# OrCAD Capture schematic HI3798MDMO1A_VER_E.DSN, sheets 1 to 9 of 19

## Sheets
1 SHEET12: size Custom
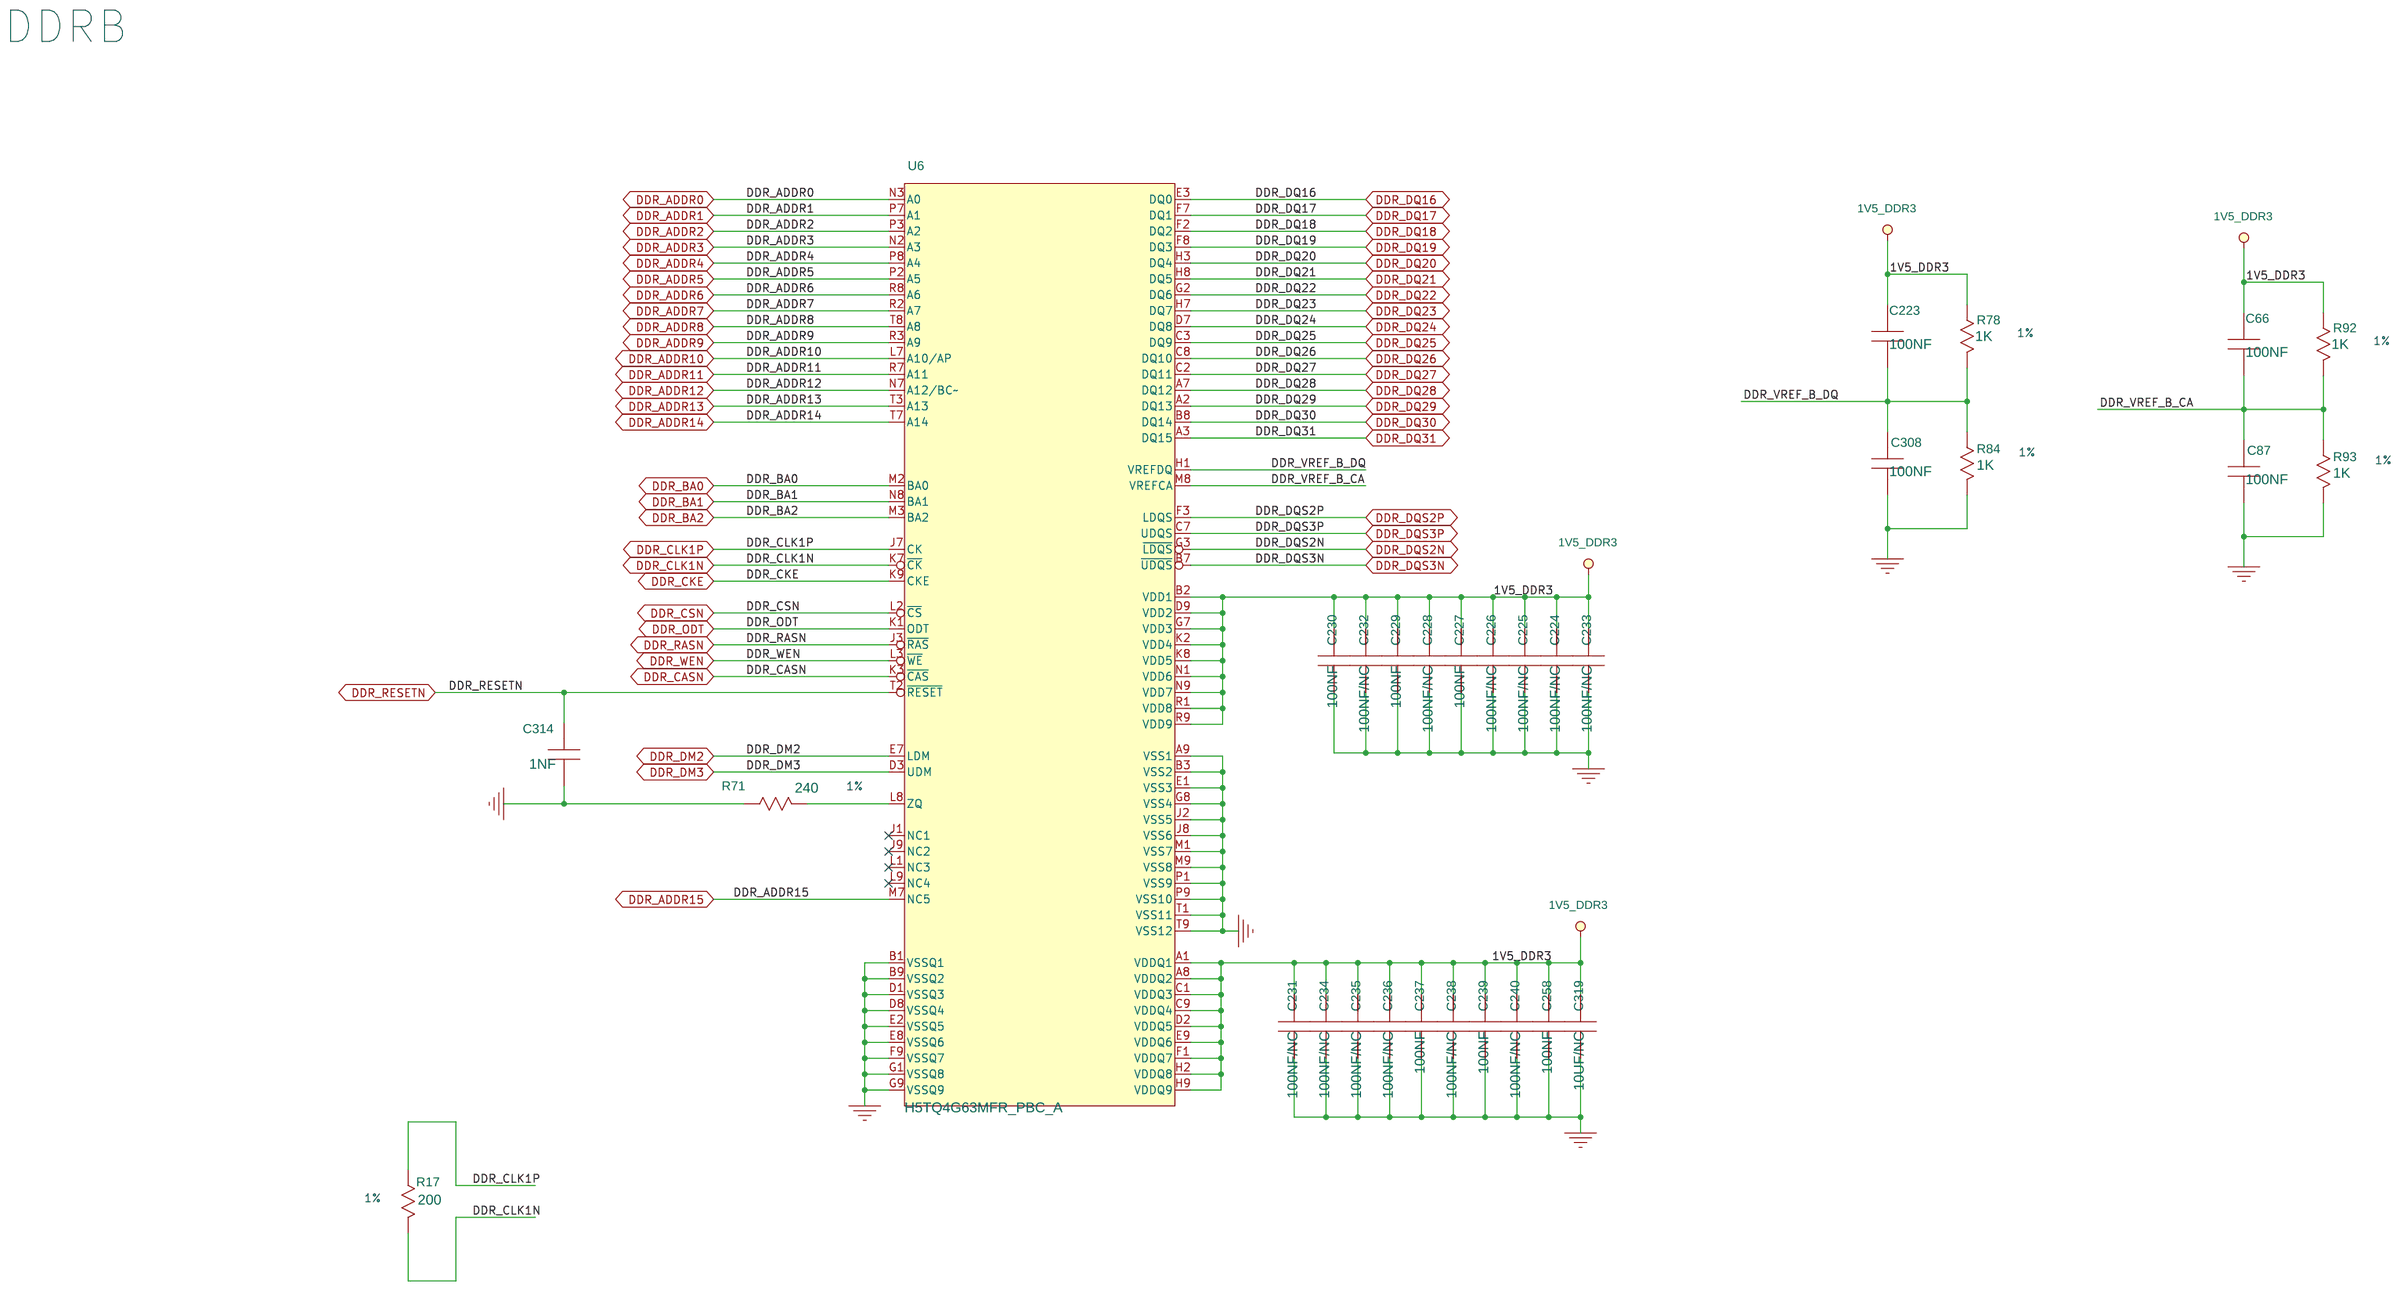
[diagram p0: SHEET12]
2 SHEET11: size Custom
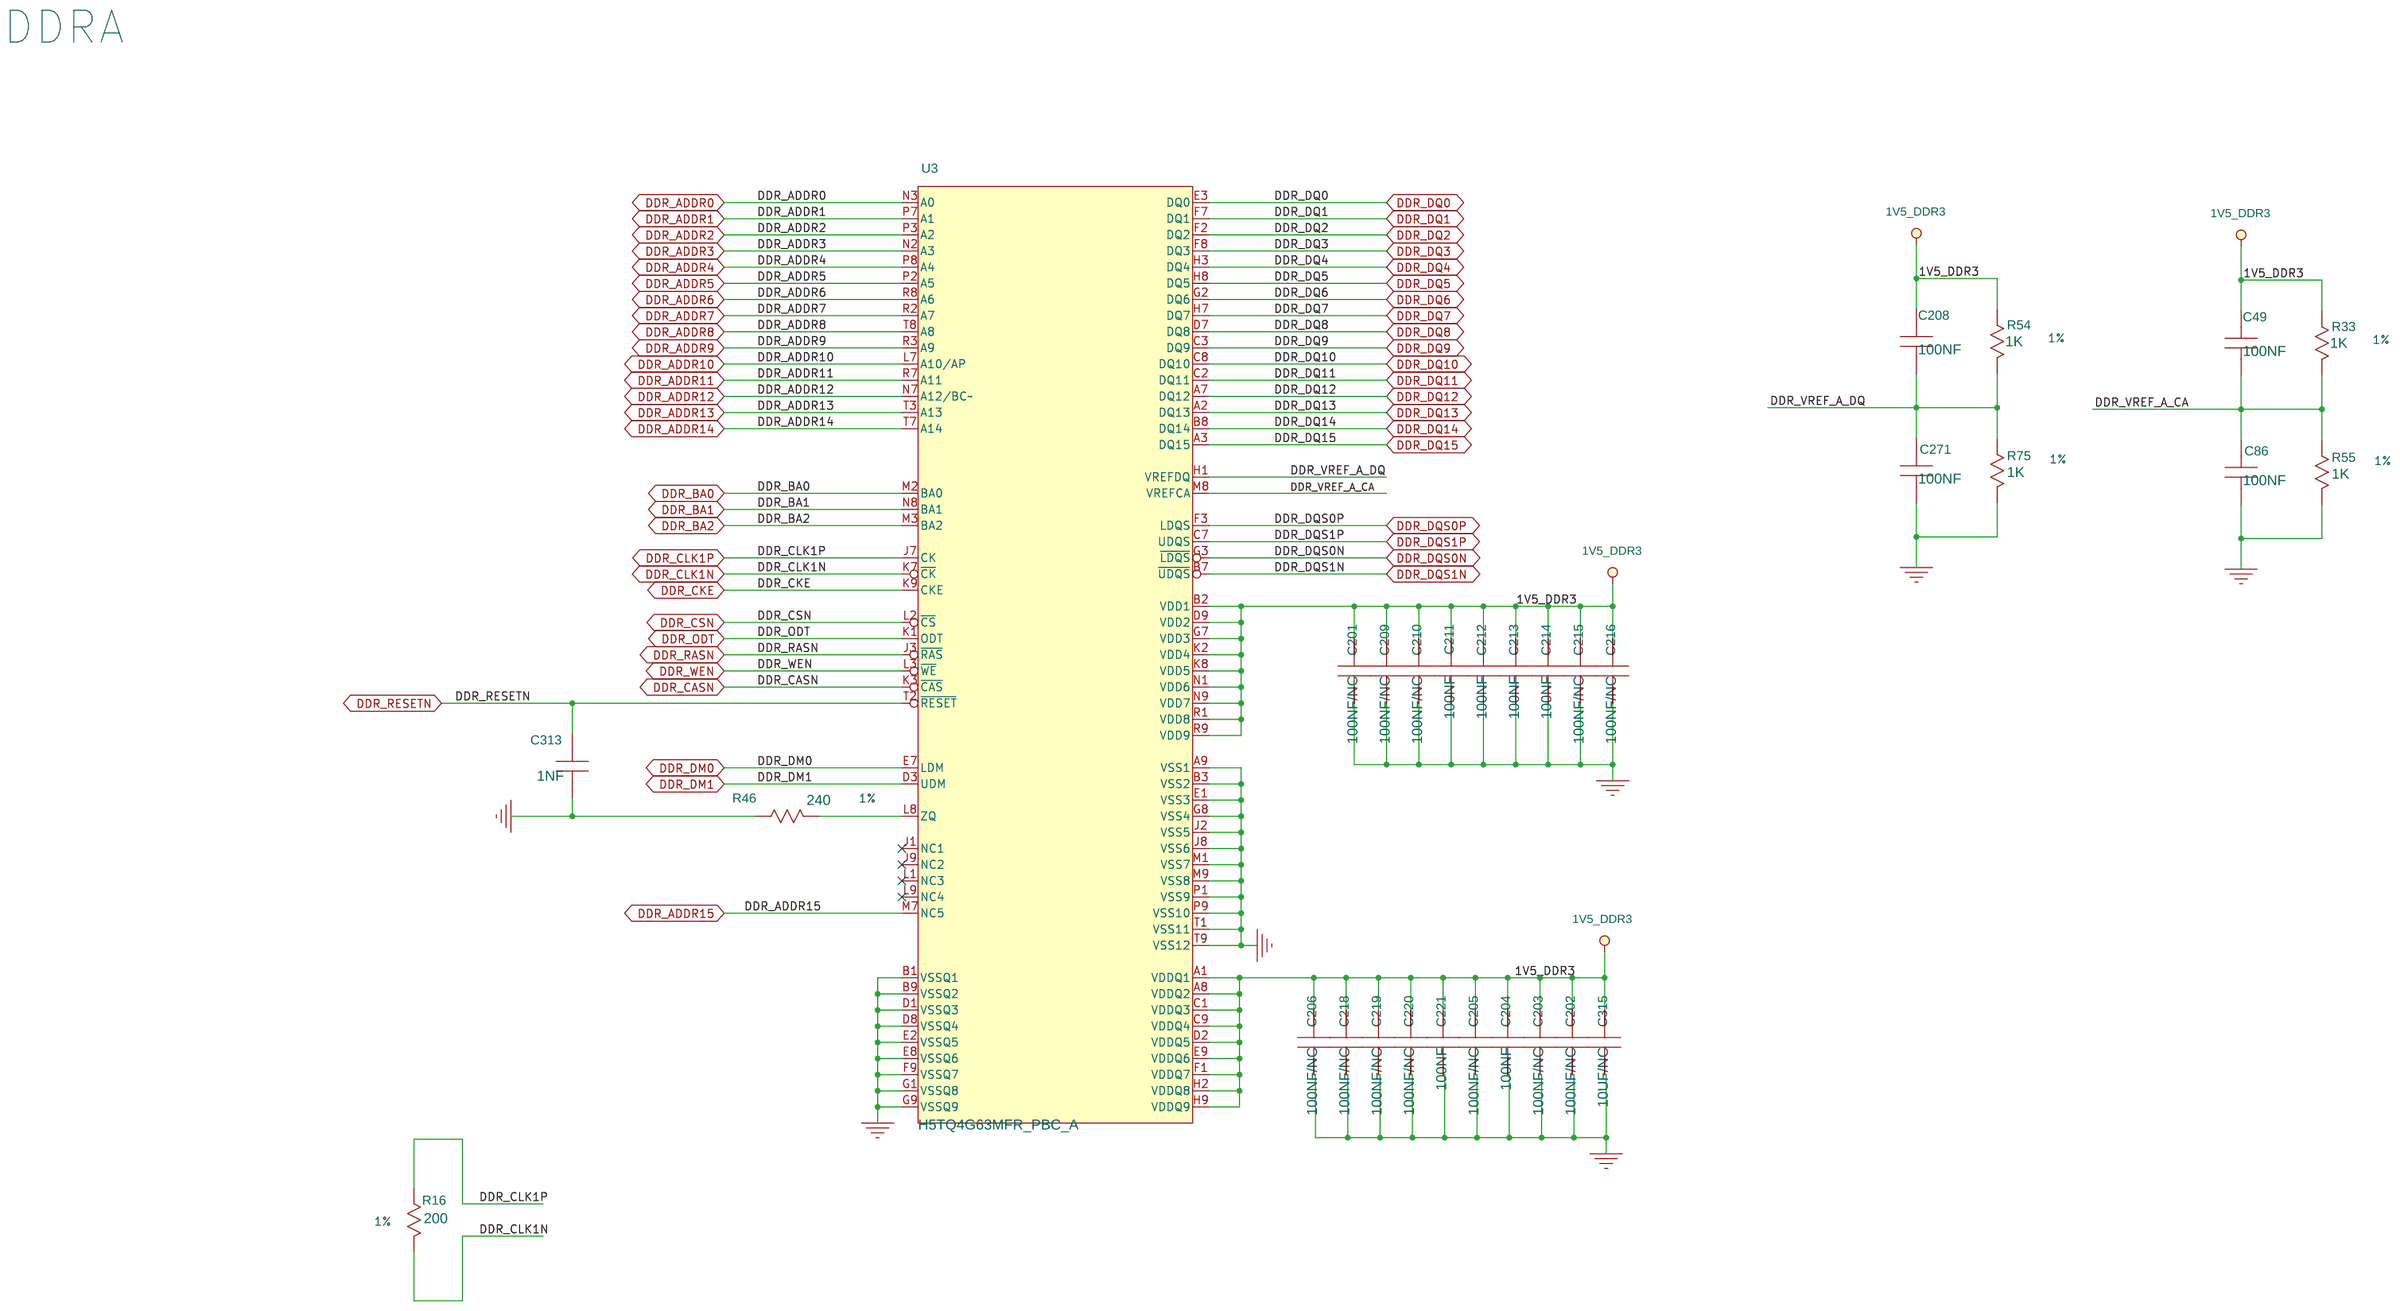
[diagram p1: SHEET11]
3 SHEET01
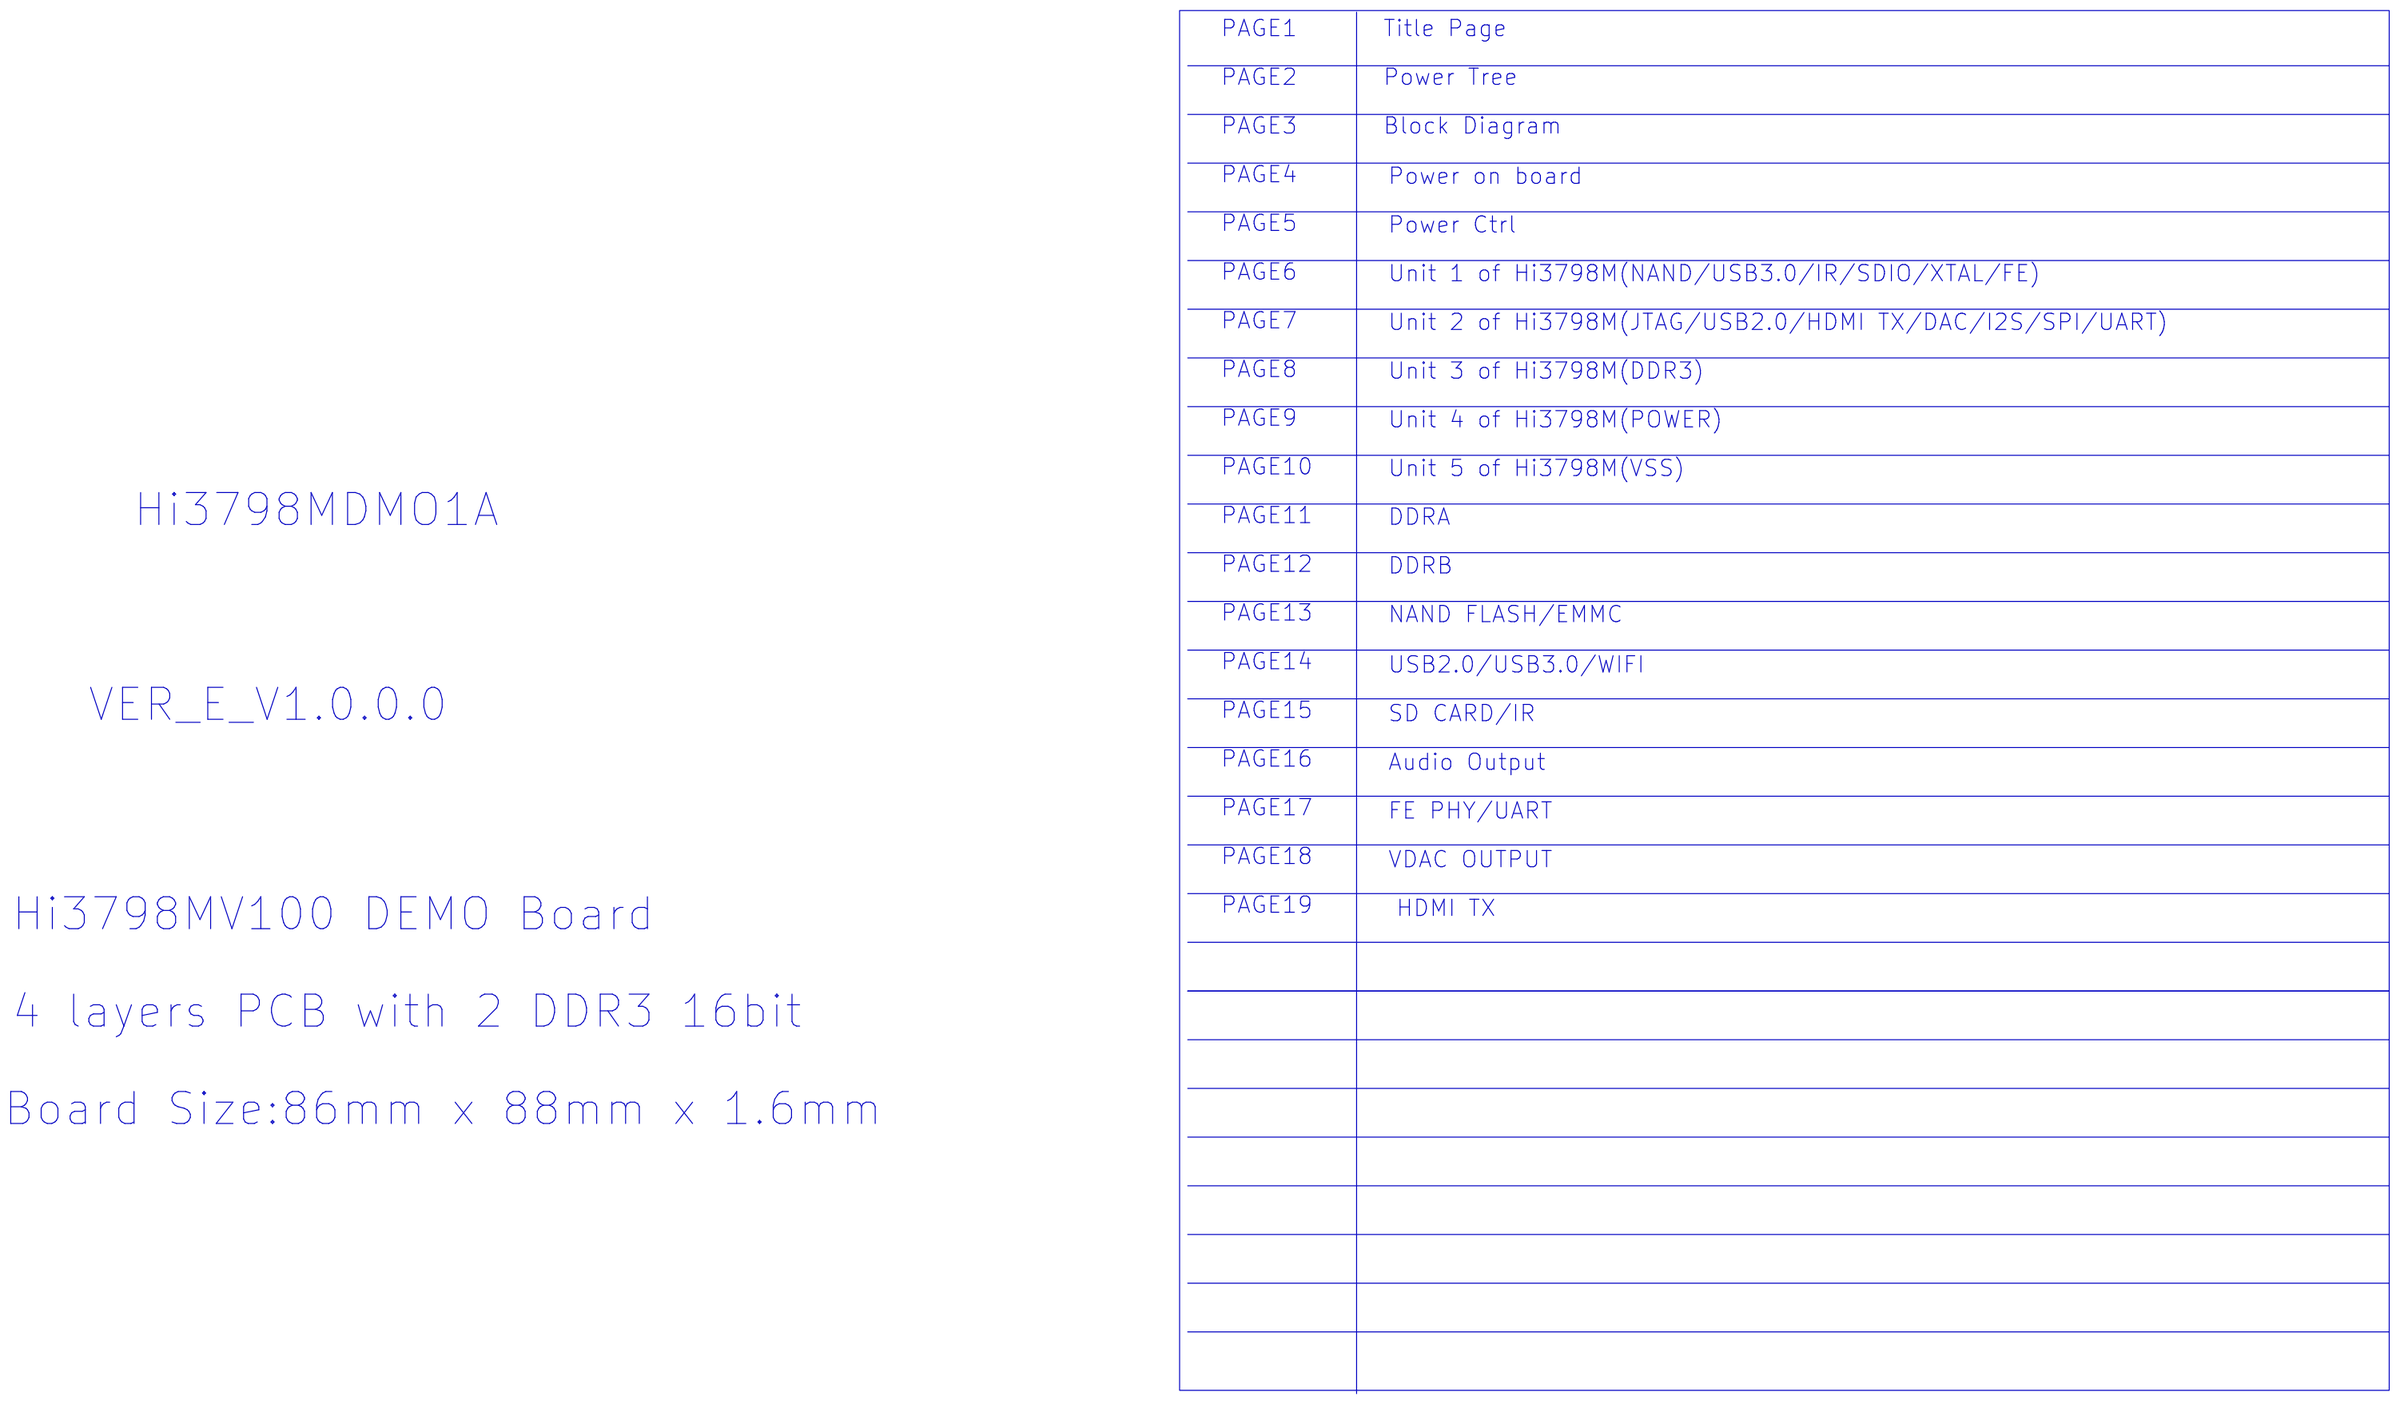
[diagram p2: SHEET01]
4 SHEET02
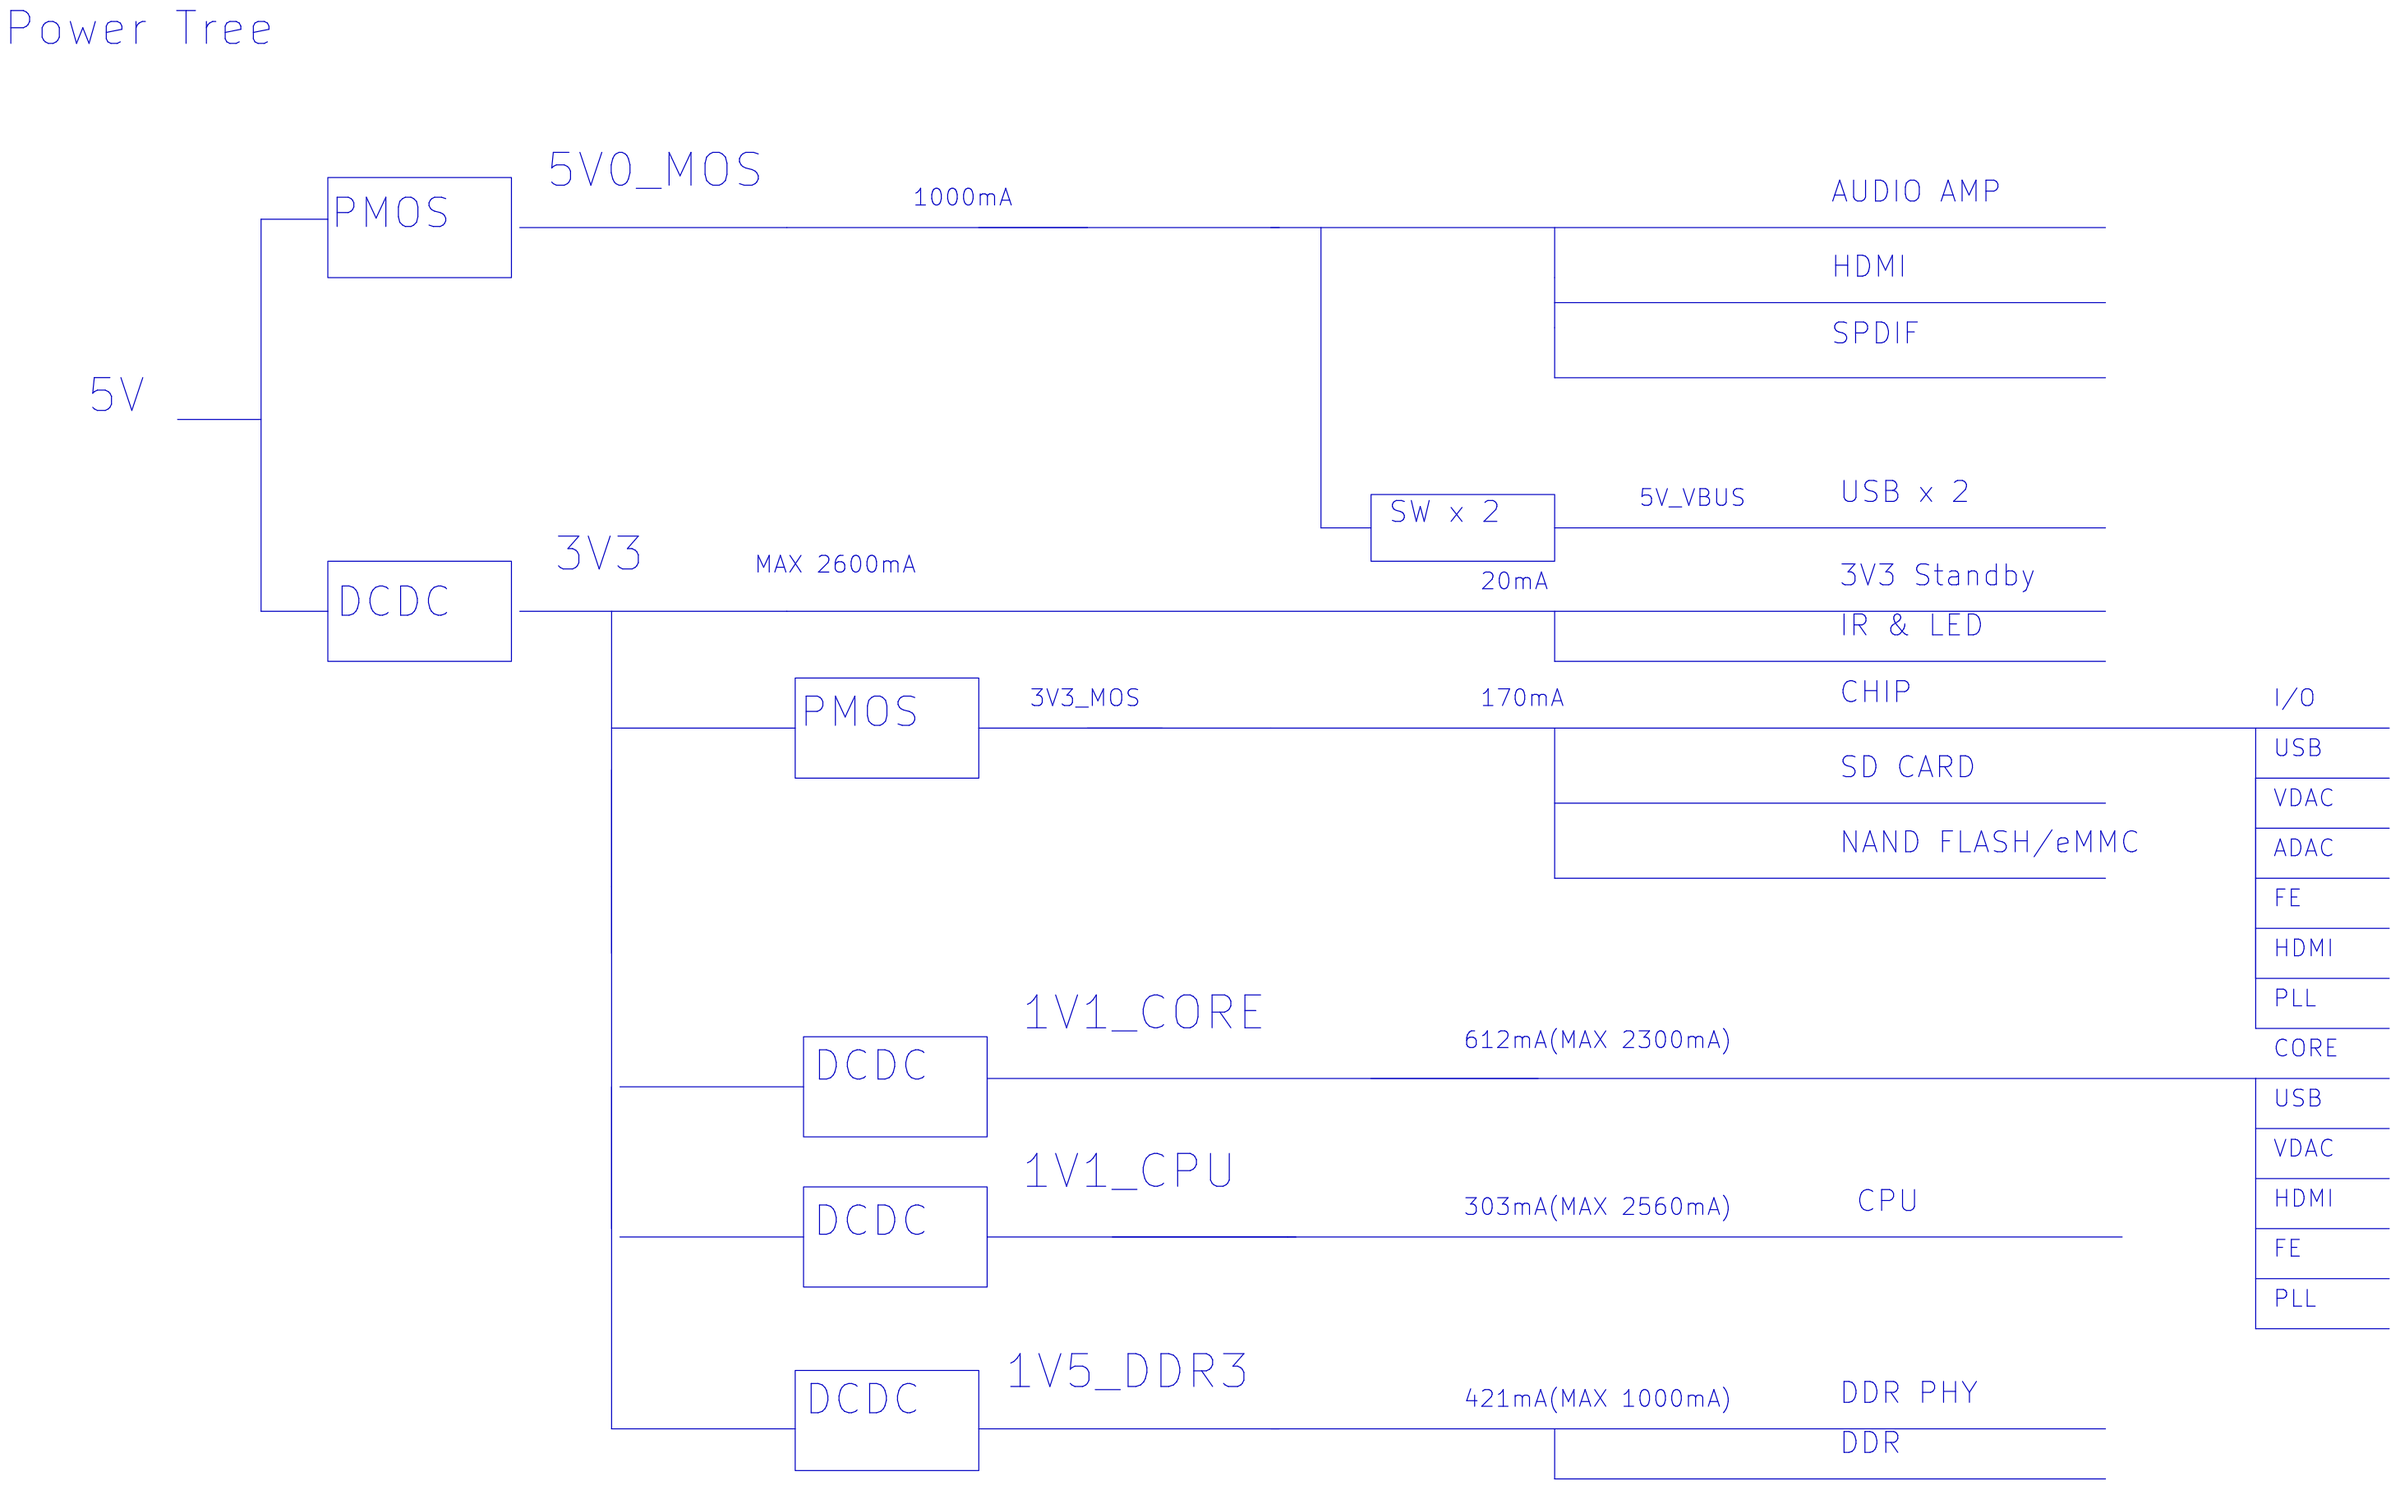
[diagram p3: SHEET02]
5 SHEET03: size B
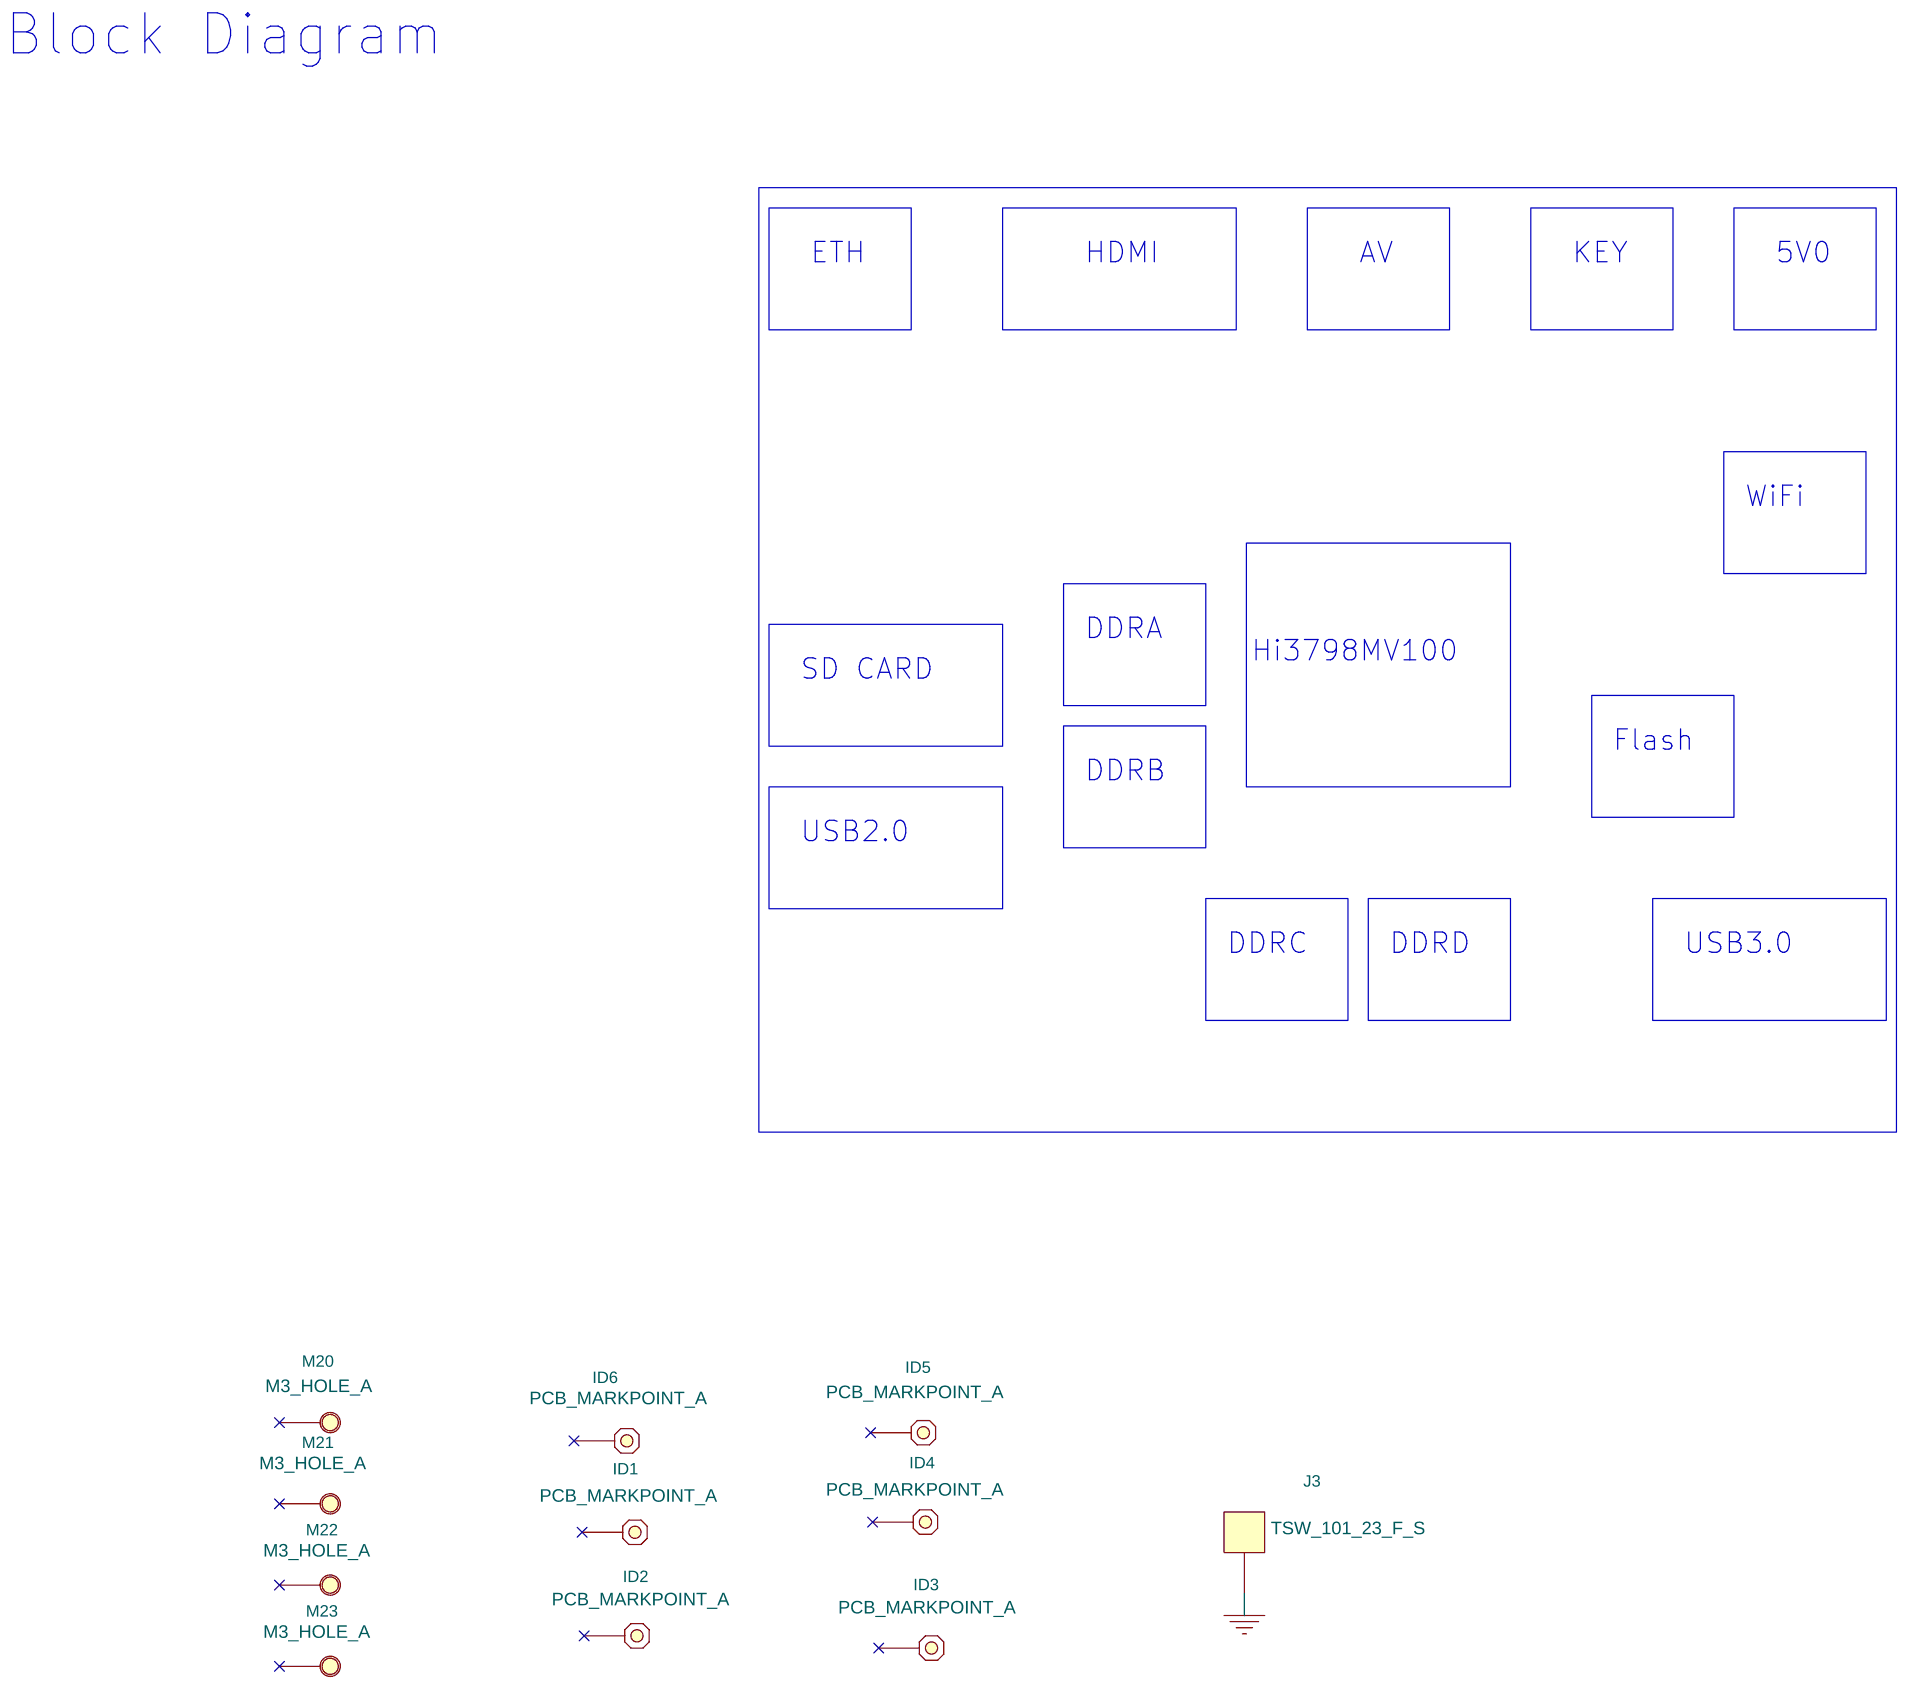
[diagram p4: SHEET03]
6 SHEET04: size Custom
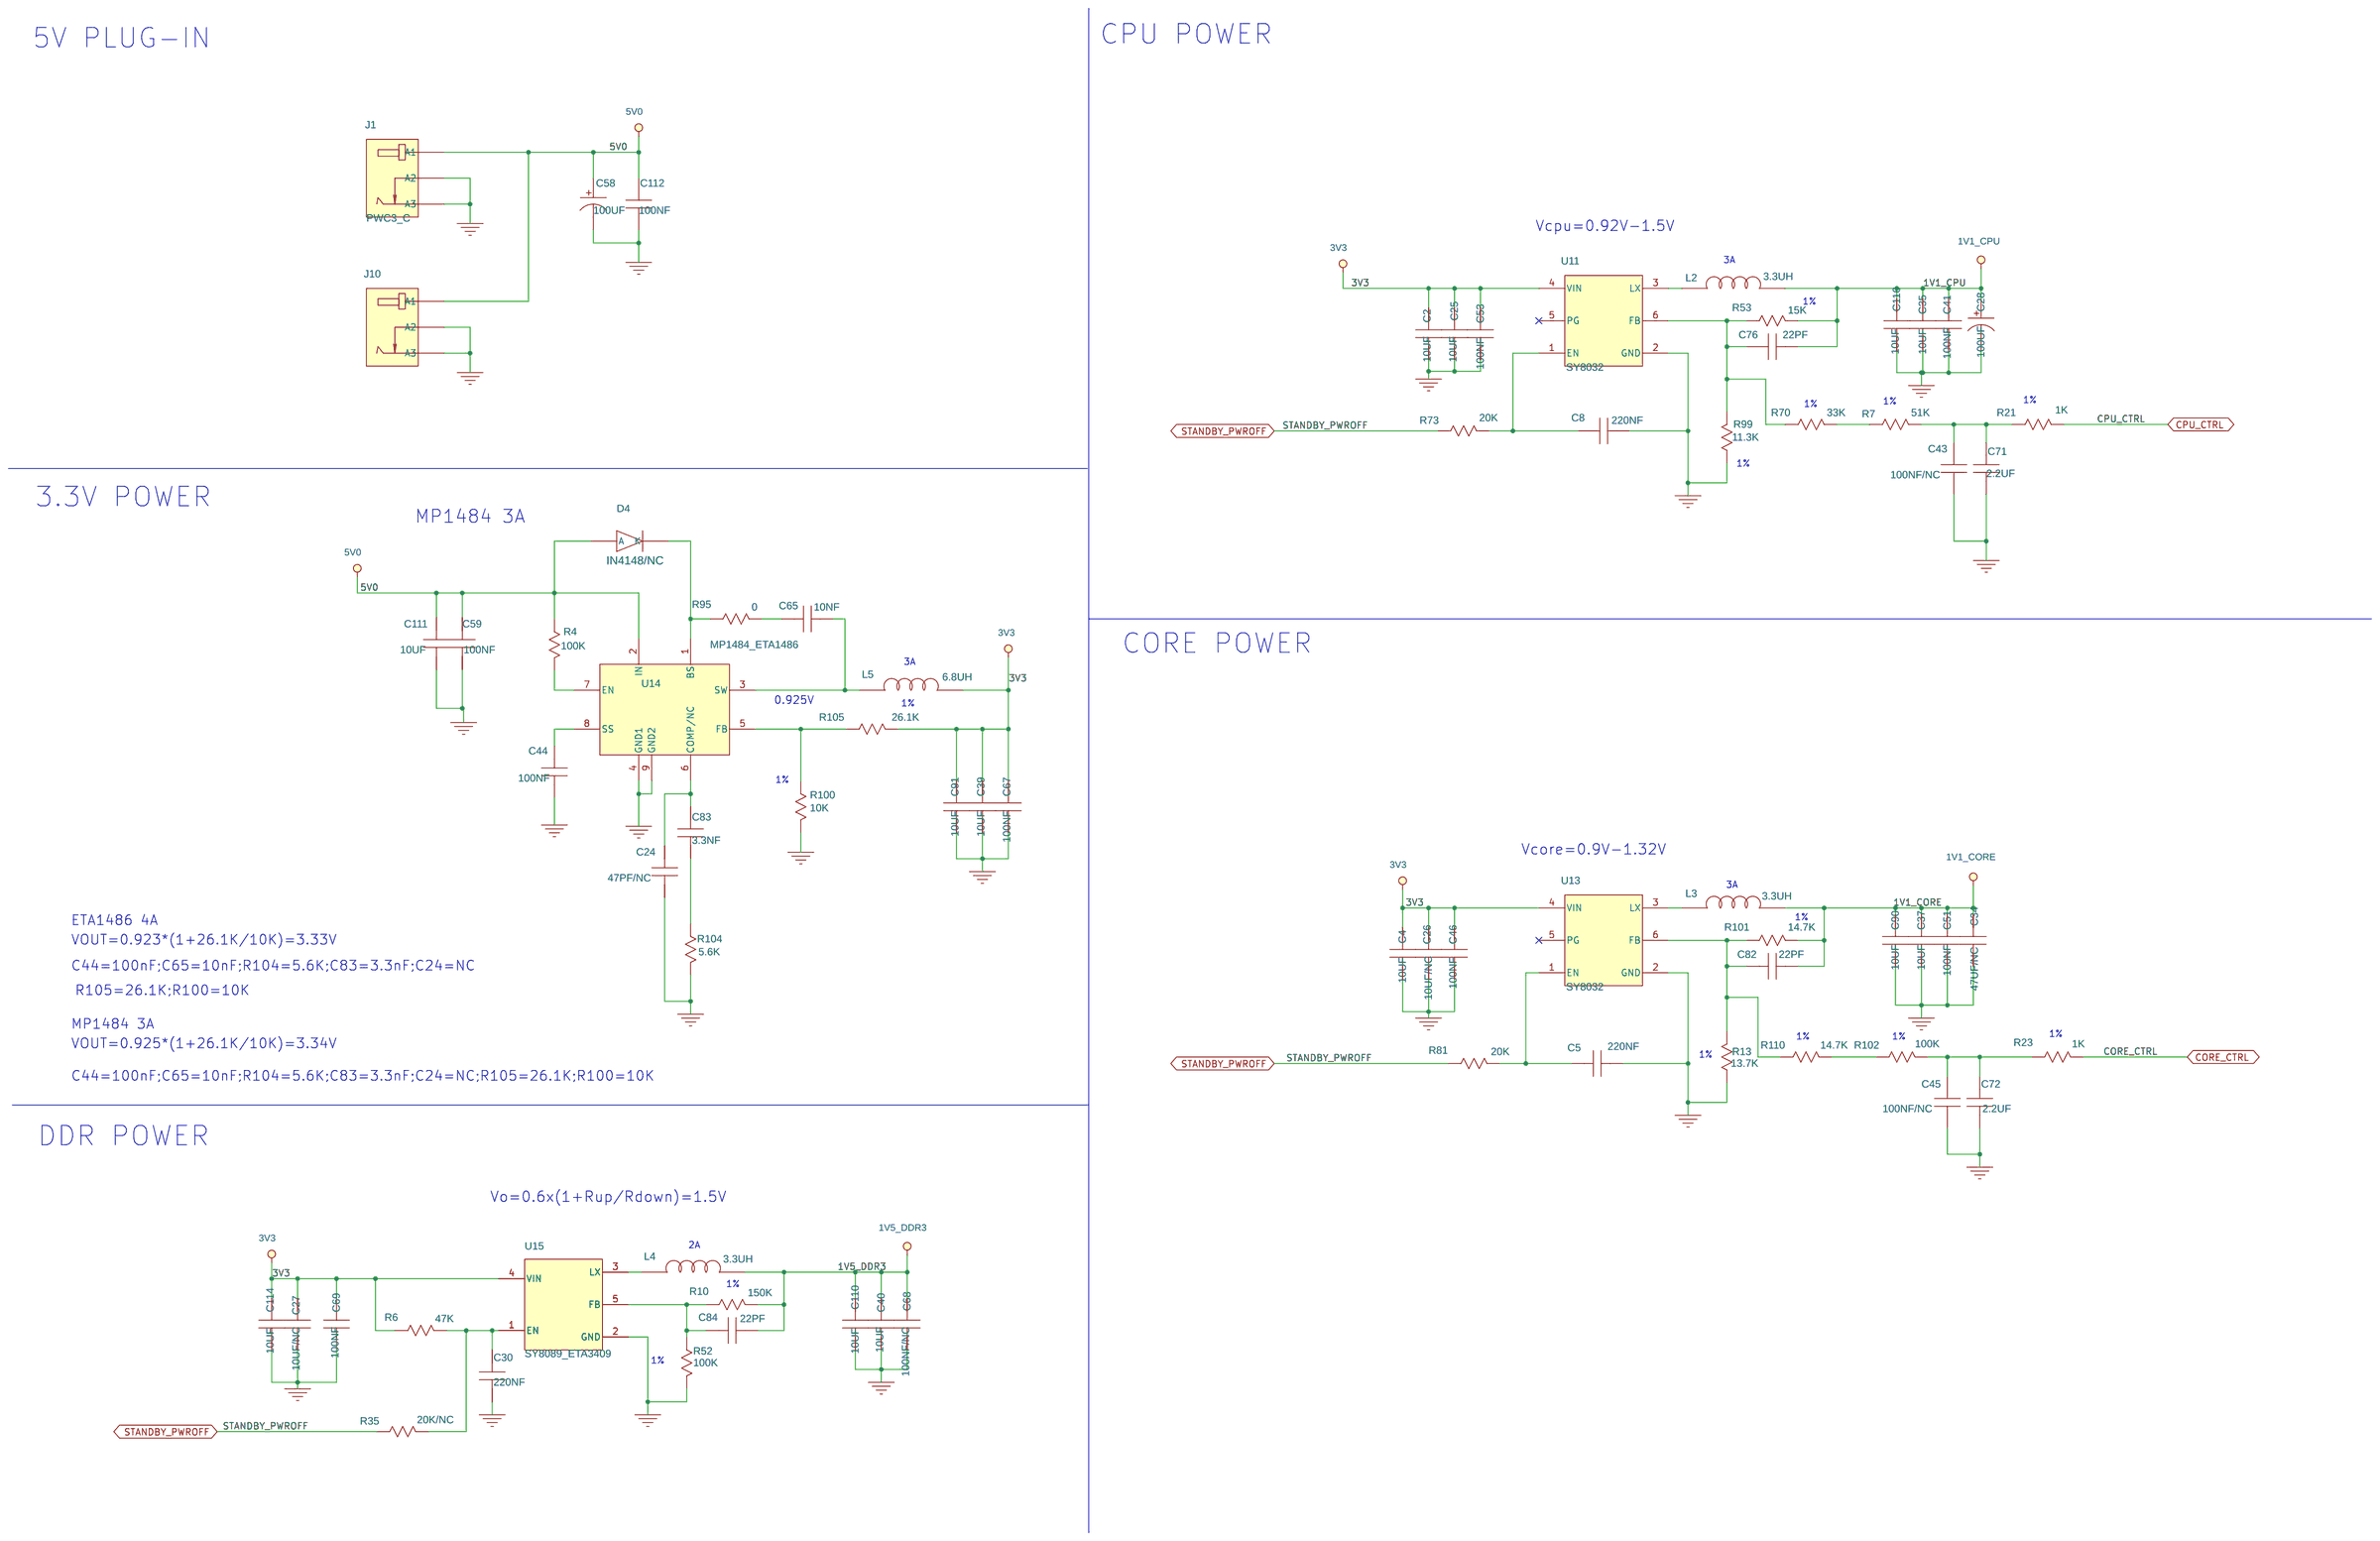
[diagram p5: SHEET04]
7 SHEET05: size A
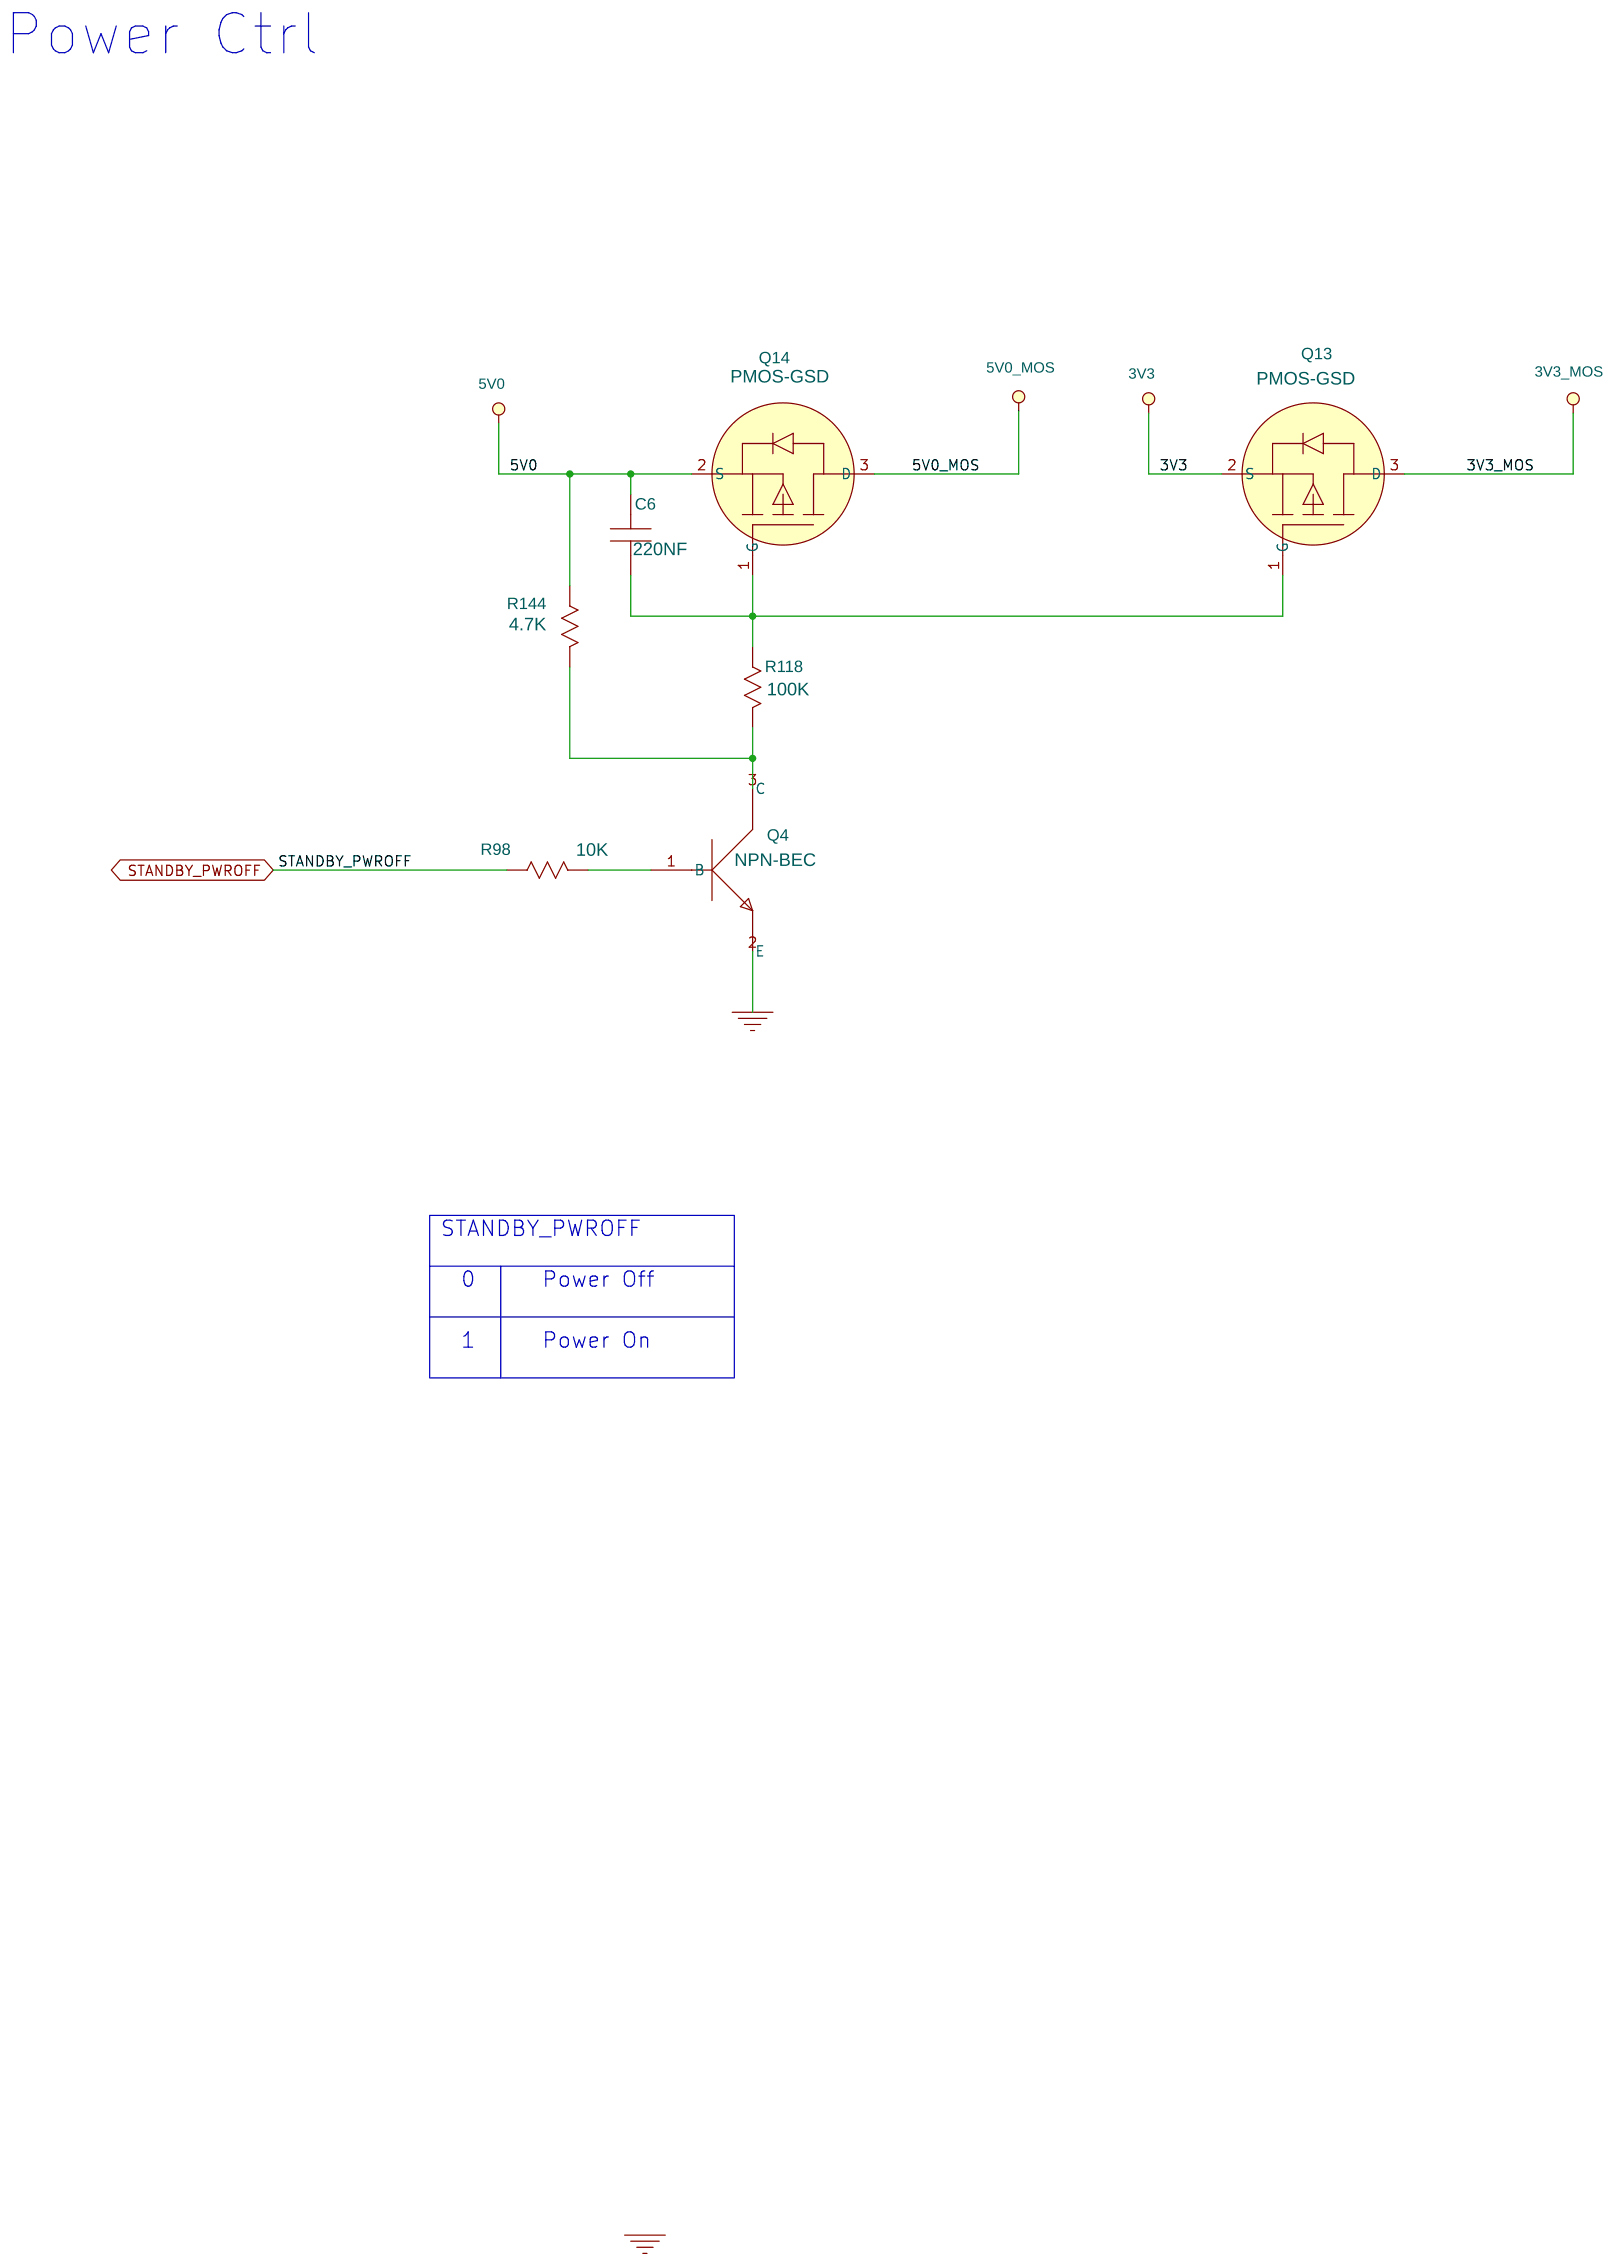
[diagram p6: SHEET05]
8 SHEET06: size Custom
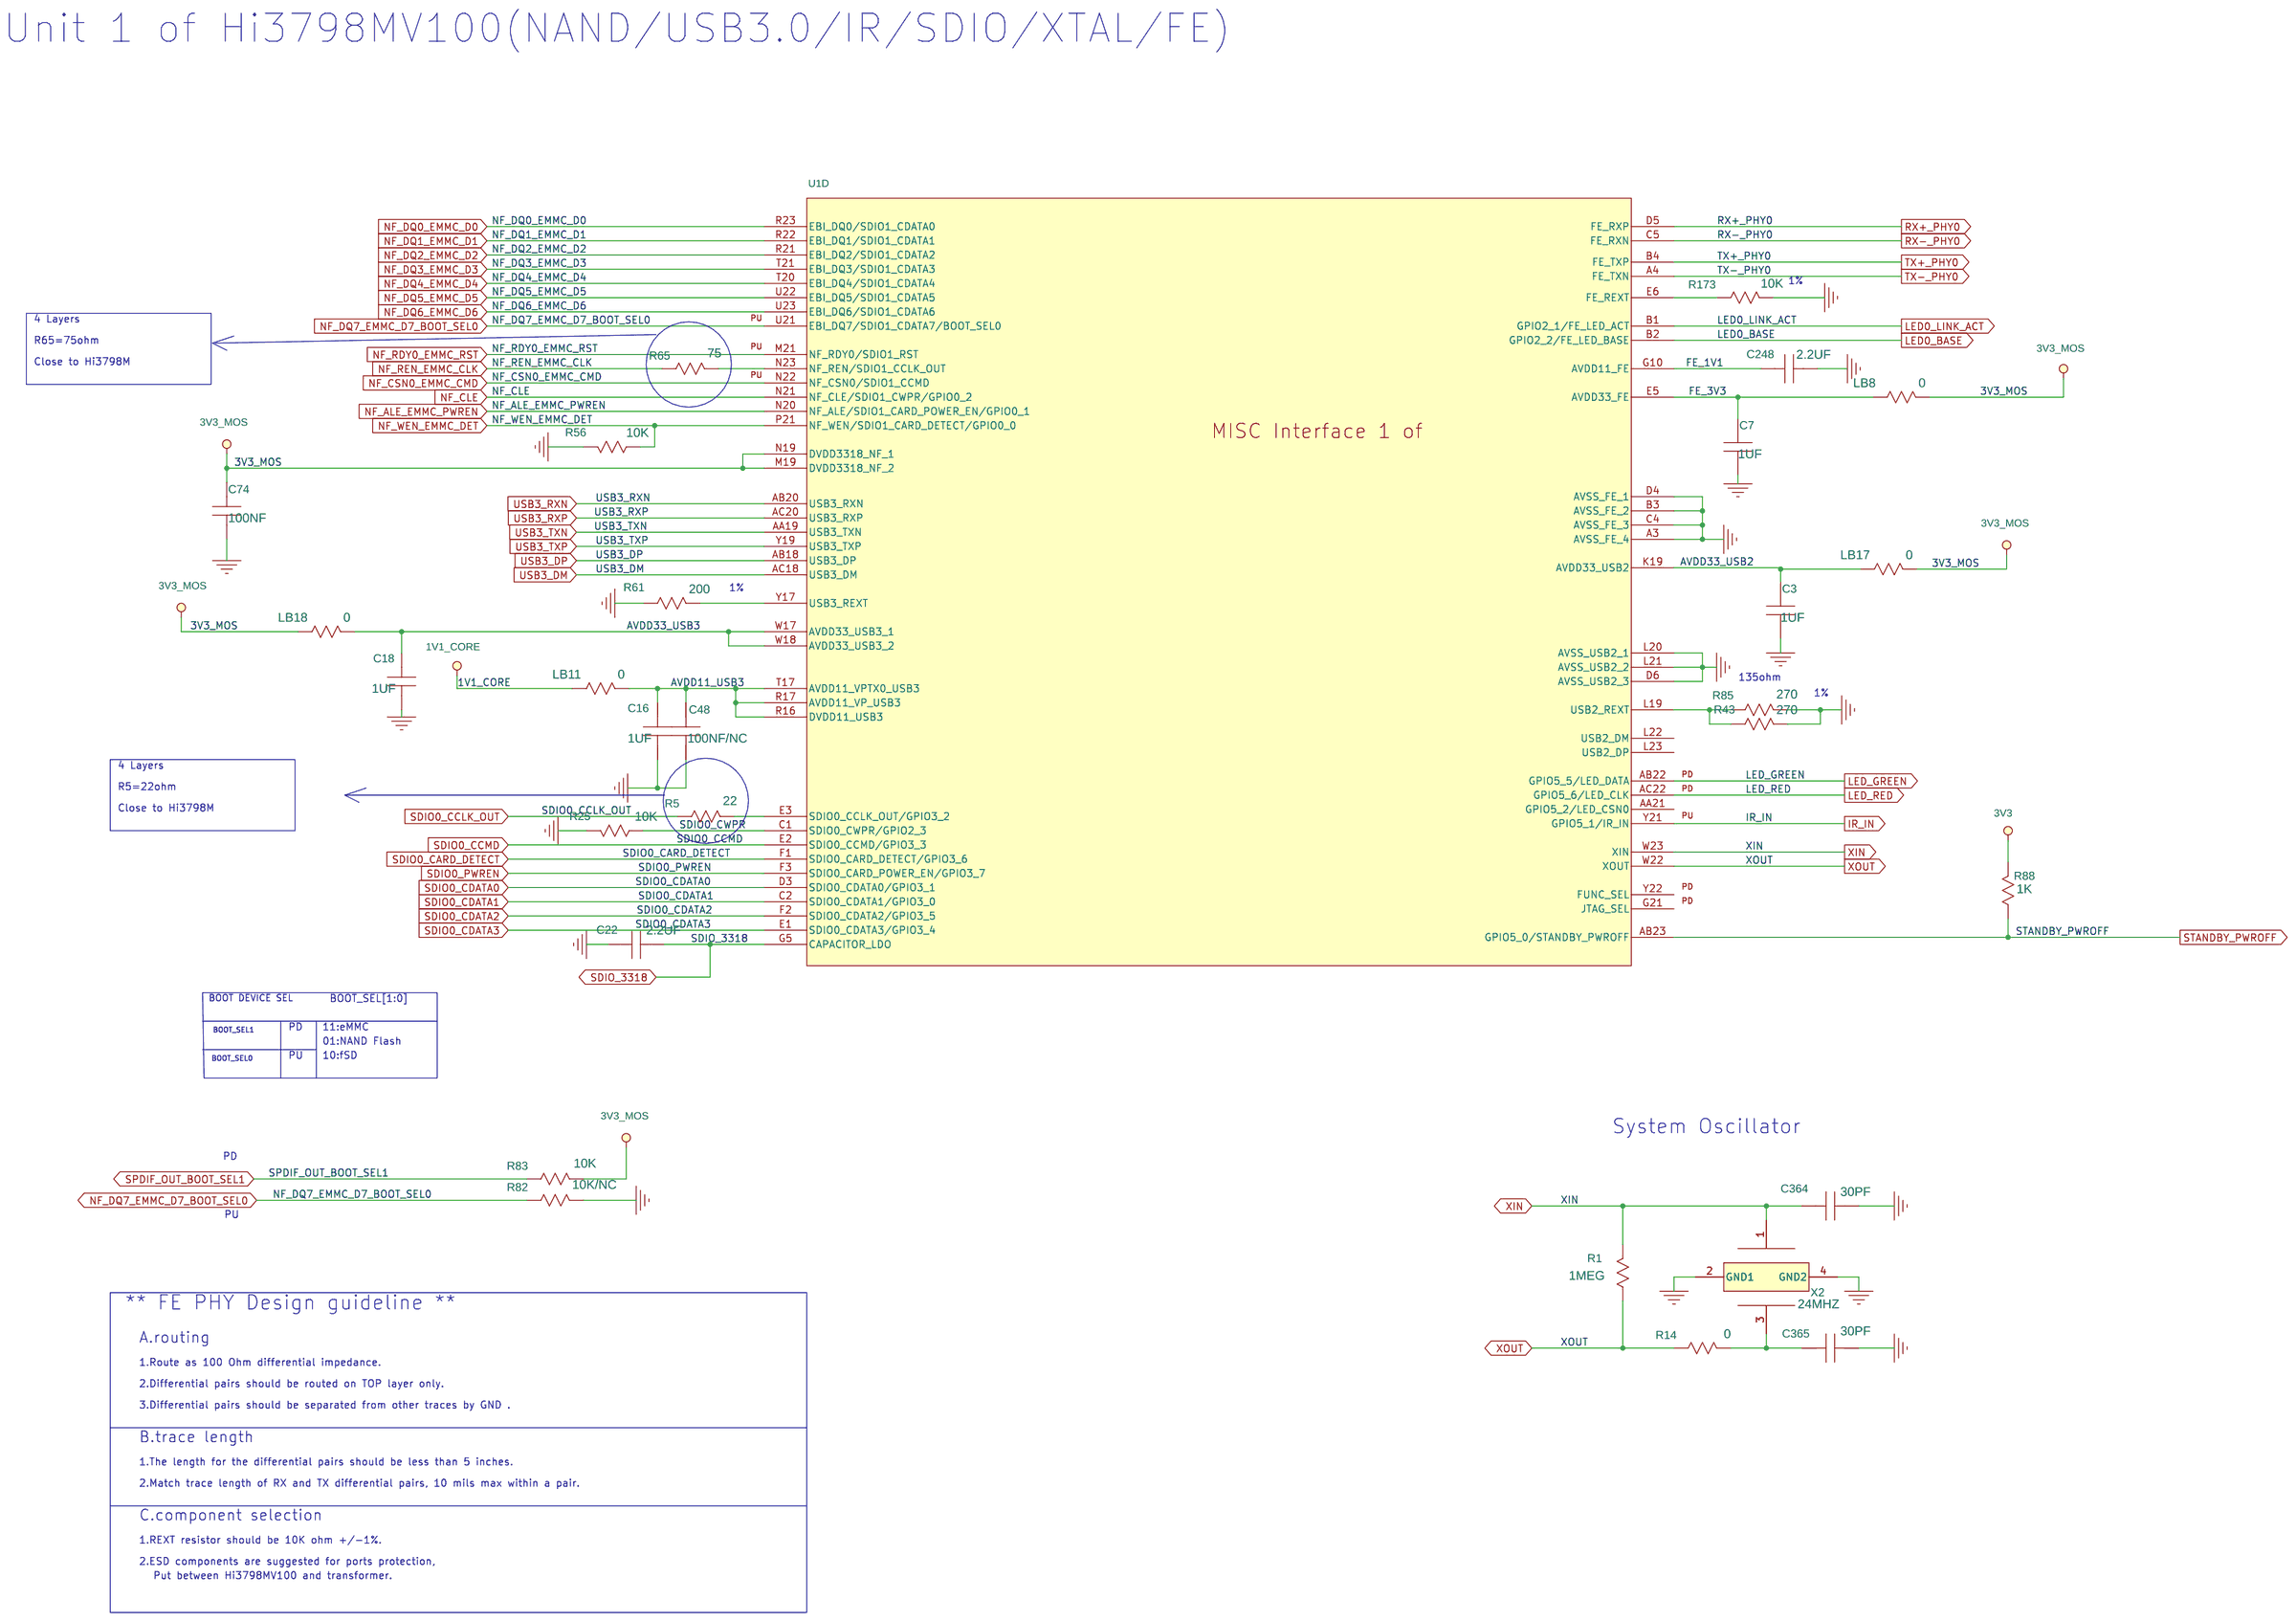
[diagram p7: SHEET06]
9 SHEET07: size Custom
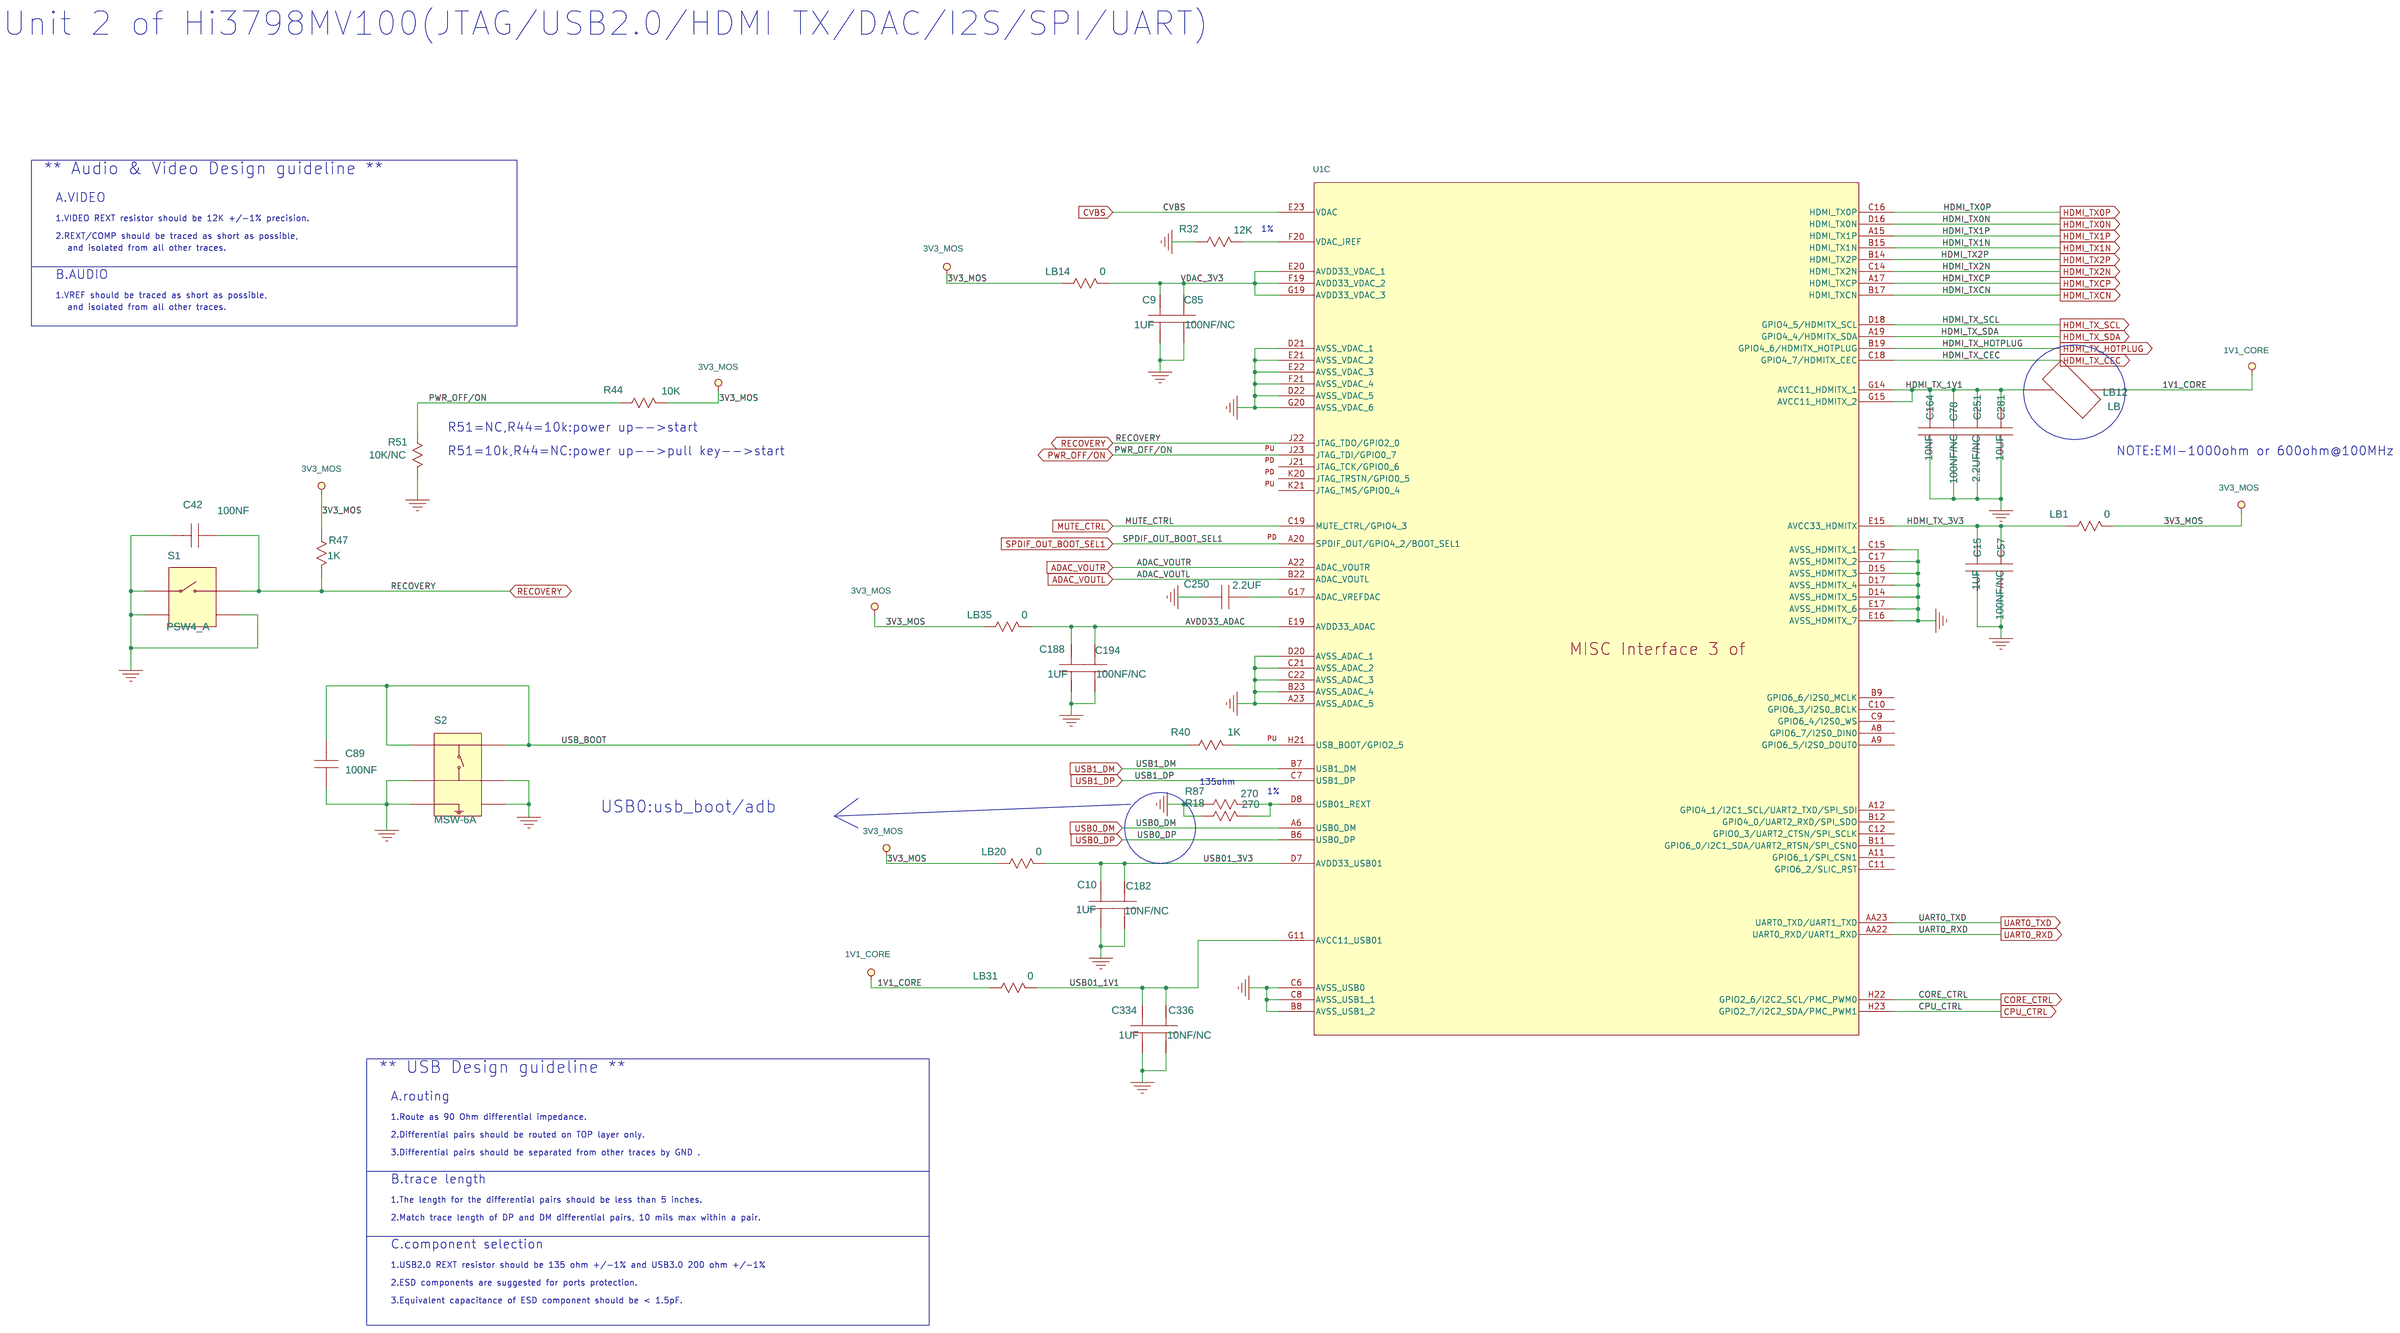
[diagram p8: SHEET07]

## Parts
sheet SHEET03
ID1  ID-BOARD  [ID-BOARD]
ID2  ID-BOARD  [ID-BOARD]
ID3  ID-BOARD  [ID-BOARD]
ID4  ID-BOARD  [ID-BOARD]
ID5  ID-BOARD  [ID-BOARD]
ID6  ID-BOARD  [ID-BOARD]
J3  NC  [SIP-1P]
M20  HOLE  [HOLE182-142]
M21  HOLE  [HOLE182-142]
M22  HOLE  [HOLE182-142]
M23  HOLE  [HOLE182-142]
sheet SHEET04
C2  10UF  [SC0805]
C4  10UF  [SC0805]
C5  220NF  [SC0402]
C8  220NF  [SC0402]
C24  47PF/NC  [SC0402]
C25  10UF  [SC0805]
C26  10UF/NC  [SC0805]
C27  10UF/NC  [SC0805]
C28  100UF  [SAC6666]
C30  220NF  [SC0402]
C34  47UF/NC  [SC1206]
C35  10UF  [SC0603]
C37  10UF  [SC0603]
C39  10UF  [SC0603]
C40  10UF  [SC0603]
C41  100NF  [SC0402]
C43  100NF/NC  [SC0402]
C44  100NF  [SC0402]
C45  100NF/NC  [SC0402]
C46  100NF  [SC0402]
C51  100NF  [SC0402]
C53  100NF  [SC0402]
C58  100UF  [SAC6666]
C59  100NF  [SC0402]
C65  10NF  [SC0402]
C67  100NF  [SC0402]
C68  100NF/NC  [SC0402]
C69  100NF  [SC0402]
C71  2.2UF  [SC0603]
C72  2.2UF  [SC0603]
C76  22PF  [SC0402]
C82  22PF  [SC0402]
C83  3.3NF  [SC0402]
C84  22PF  [SC0402]
C90  10UF  [SC0603]
C91  10UF  [SC0603]
C110  10UF  [SC0603]
C111  10UF  [SC0805]
C112  100NF  [SC0402]
C114  10UF  [SC0805]
C116  10UF  [SC0603]
D4  IN4148/NC  [HSOD323A]
J1  PWC3_C  [PWC3-RF-A]
J10  NC  [DC-002]
L2  3.3UH  [SWPA4020S]
L3  3.3UH  [SWPA4020S]
L4  3.3UH  [SWPA4020S]
L5  6.8UH  [SWPA5040S]
R4  100K  [SR0402]
R6  47K  [SR0402]
R7  51K  [SR0402]
R10  150K  [SR0402]
R13  13.7K  [SR0402]
R21  1K  [SR0402]
R23  1K  [SR0402]
R35  20K/NC  [SR0402]
R52  100K  [SR0402]
R53  15K  [SR0402]
R70  33K  [SR0402]
R73  20K  [SR0402]
R81  20K  [SR0402]
R95  0  [SR0402]
R99  11.3K  [SR0402]
R100  10K  [SR0402]
R101  14.7K  [SR0402]
R102  100K  [SR0402]
R104  5.6K  [SR0402]
R105  26.1K  [SR0402]
R110  14.7K  [SR0402]
U11  SY8032  [SOT23_6]
U13  SY8032  [SOT23_6]
U14  MP1484_ETA1486  [SOIC8N]
U15  SY8089_ETA3409  [SOT23_5]
sheet SHEET05
C6  220NF  [SC0603]
Q4  NPN-BEC  [SOT23]
Q13  PMOS-GSD  [SOT23]
Q14  PMOS-GSD  [SOT23]
R98  10K  [SR0402]
R118  100K  [SR0402]
R144  4.7K  [SR0402]
sheet SHEET06
C3  1UF  [SC0603]
C7  1UF  [SC0603]
C16  1UF  [SC0603]
C18  1UF  [SC0603]
C22  2.2UF  [HSC0402]
C48  100NF/NC  [SC0402]
C74  100NF  [SC0402]
C248  2.2UF  [HSC0402]
C364  30PF  [SC0402]
C365  30PF  [SC0402]
LB8  0  [SL0402]
LB11  0  [SL0402]
LB17  0  [SL0603]
LB18  0  [SL0402]
R1  1MEG  [SR0603]
R5  22  [SR0402]
R14  0  [SR0402]
R25  10K  [SR0402]
R43  270  [SR0402]
R56  10K  [SR0402]
R61  200  [SR0402]
R65  75  [SR0402]
R82  10K/NC  [SR0402]
R83  10K  [SR0402]
R85  270  [SR0402]
R88  1K  [SR0402]
R173  10K  [SR0402]
X2  24MHZ  [X288]
sheet SHEET07
C9  1UF  [SC0603]
C10  1UF  [SC0603]
C15  1UF  [SC0402]
C42  100NF  [SC0402]
C57  100NF/NC  [SC0402]
C78  100NF/NC  [SC0402]
C85  100NF/NC  [SC0402]
C89  100NF  [SC0402]
C164  10NF  [SC0402]
C182  10NF/NC  [SC0402]
C188  1UF  [SC0603]
C194  100NF/NC  [SC0402]
C250  2.2UF  [HSC0402]
C251  2.2UF/NC  [SC0603]
C281  10UF  [SC0603]
C334  1UF  [SC0402]
C336  10NF/NC  [SC0402]
LB1  0  [SL0402]
LB12  LB  [SL0402]
LB14  0  [SL0603]
LB20  0  [SL0402]
LB31  0  [SL0402]
LB35  0  [SL0402]
R18  270  [SR0402]
R32  12K  [SR0402]
R40  1K  [SR0402]
R44  10K  [SR0402]
R47  1K  [SR0402]
R51  10K/NC  [SR0402]
R87  270  [SR0402]
S1  PSW4_A  [TSW4-RG-C]
S2  MSW-6A  [SPSW6-T]
sheet SHEET09
U1  S40V300_19X19  [TFBGA395-32-2323]  (sections A,B,C,D,E)
sheet SHEET11
C49  100NF  [SC0402]
C86  100NF  [SC0402]
C201  100NF/NC  [SC0402]
C202  100NF/NC  [SC0402]
C203  100NF/NC  [SC0402]
C204  100NF  [SC0402]
C205  100NF/NC  [SC0402]
C206  100NF/NC  [SC0402]
C208  100NF  [SC0402]
C209  100NF/NC  [SC0402]
C210  100NF/NC  [SC0402]
C211  100NF  [SC0402]
C212  100NF  [SC0402]
C213  100NF  [SC0402]
C214  100NF  [SC0402]
C215  100NF/NC  [SC0402]
C216  100NF/NC  [SC0402]
C218  100NF/NC  [SC0402]
C219  100NF/NC  [SC0402]
C220  100NF/NC  [SC0402]
C221  100NF  [SC0402]
C271  100NF  [SC0402]
C313  1NF  [SC0402]
C315  10UF/NC  [SC0805]
R16  200  [SR0402]
R33  1K  [SR0402]
R46  240  [SR0402]
R54  1K  [SR0402]
R55  1K  [SR0402]
R75  1K  [SR0402]
U3  H5TQ4G63MFR_PBC_A  [BGA96-32-1609I]
sheet SHEET12
C66  100NF  [SC0402]
C87  100NF  [SC0402]
C223  100NF  [SC0402]
C224  100NF/NC  [SC0402]
C225  100NF/NC  [SC0402]
C226  100NF/NC  [SC0402]
C227  100NF  [SC0402]
C228  100NF/NC  [SC0402]
C229  100NF  [SC0402]
C230  100NF  [SC0402]
C231  100NF/NC  [SC0402]
C232  100NF/NC  [SC0402]
C233  100NF/NC  [SC0402]
C234  100NF/NC  [SC0402]
C235  100NF/NC  [SC0402]
C236  100NF/NC  [SC0402]
C237  100NF  [SC0402]
C238  100NF/NC  [SC0402]
C239  100NF  [SC0402]
C240  100NF/NC  [SC0402]
C258  100NF  [SC0402]
C308  100NF  [SC0402]
C314  1NF  [SC0402]
C319  10UF/NC  [SC0805]
R17  200  [SR0402]
R71  240  [SR0402]
R78  1K  [SR0402]
R84  1K  [SR0402]
R92  1K  [SR0402]
R93  1K  [SR0402]
U6  H5TQ4G63MFR_PBC_A  [BGA96-32-1609I]

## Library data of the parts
ID1-ID6 = ID-BOARD: %195%%232%%202%%246%: PCB-MARK点ID-BOARD，亮铜直径40MIL，阻焊开窗直径80MIL，MARK点大小120MIL。; DEVICE: PCB_MARKPOINT_A
J3 = SIP1: %195%%232%%202%%246%: 插针-普通方脚插针-1PIN-单排-直式-5.84MM-2.92MM-2.54MM-THT; %208%%161%%192%%224%%195%%251%%179%%198%: 插针; CODE: 14050101; DEVICE: TSW_101_23_F_S
M20-M23 = HOLE: %195%%232%%202%%246%: 自建封装; DEVICE: M3_HOLE_A
C2 C4 C25-C27 C111 C114 = C: %182%%238%%182%%168%%185%%164%%215%%247%%181%%231%%209%%185%(V): 25; %195%%232%%202%%246%: SMD陶瓷电容-25V-10000NF-+/-20%-X5R-0805; %208%%161%%192%%224%%195%%251%%179%%198%: SMD陶瓷电容; CODE: 8071629; COMPONENT_HIGH_MAX: 1.45MM; DEVICE: C2012X5R1E106KT000N1
C5 C8 C30 = C: %182%%238%%182%%168%%185%%164%%215%%247%%181%%231%%209%%185%(V): 6.3; %195%%232%%202%%246%: SMD陶瓷电容-6.3V-220NF-+/-10%-X5R-0402-BT; %208%%161%%192%%224%%195%%251%%179%%198%: SMD陶瓷电容; CODE: 8070584; COMPONENT_HIGH_MAX: 0.55MM; DEVICE: GRM155R60J224KE01D
C24 = C: %182%%238%%182%%168%%185%%164%%215%%247%%181%%231%%209%%185%(V): 50; %195%%232%%202%%246%: SMD陶瓷电容-50V-0.047NF-±5%-NP0-0402; %208%%161%%192%%224%%195%%251%%179%%198%: SMD陶瓷电容; CODE: 8070549; COMPONENT_HIGH_MAX: 0.55MM; DEVICE: C0402C470J5GAC_7867
C28 C58 = CP: %182%%238%%182%%168%%185%%164%%215%%247%%181%%231%%209%%185%(V): 16; %195%%232%%202%%246%: 非固体SMD铝电容-16V-100UF-+/-20%-6.3*5.4MM-极性-105DEGC-1000H-片式,温度敏感器件-工艺耐温250DEGC,5S; %208%%161%%192%%224%%195%%251%%179%%198%: 非固体SMD铝电容; CODE: 8010269; COMPONENT_HIGH_MAX: 5.7MM; DEVICE: UWT1C101MCL1GB
C34 = C: %182%%238%%182%%168%%185%%164%%215%%247%%181%%231%%209%%185%(V): 16; %195%%232%%202%%246%: SMD陶瓷电容-16V-100NF-±10%-X7R-0402; %208%%161%%192%%224%%195%%251%%179%%198%: SMD陶瓷电容; CODE: 08070680; COMPONENT_HIGH_MAX: 1.9MM; DEVICE: CM316X5R476M06AT
C35 C37 C39 C40 C90 C91 C110 C116 C281 = C: %182%%238%%182%%168%%185%%164%%215%%247%%181%%231%%209%%185%(V): 6.3; %195%%232%%202%%246%: SMD陶瓷电容-6.3V-10000NF-+/-20%-X5R-0603-BT,TS16949; %208%%161%%192%%224%%195%%251%%179%%198%: SMD陶瓷电容; CODE: 8070649; COMPONENT_HIGH_MAX: 0.9MM; DEVICE: C1608X5R0J106MT0A0E
C41 C43 C45 C46 C51 C53 C59 C67-C69 C112 = C: %182%%238%%182%%168%%185%%164%%215%%247%%181%%231%%209%%185%(V): 16; %195%%232%%202%%246%: SMD陶瓷电容-16V-100NF-±10%-X7R-0402; %208%%161%%192%%224%%195%%251%%179%%198%: SMD陶瓷电容; CODE: 8070614; COMPONENT_HIGH_MAX: 0.6MM; DEVICE: RMEMK105BJ104KV_FR
C44 = C: %182%%238%%182%%168%%185%%164%%215%%247%%181%%231%%209%%185%(V): 16; %195%%232%%202%%246%: SMD陶瓷电容-16V-10NF-+/-10%-X7R-0402; %208%%161%%192%%224%%195%%251%%179%%198%: SMD陶瓷电容; CODE: 8070449; COMPONENT_HIGH_MAX: 0.55MM; DEVICE: GRM155R71C103KA01D
C65 = C: %182%%238%%182%%168%%185%%164%%215%%247%%181%%231%%209%%185%(V): 10; %195%%232%%202%%246%: SMD陶瓷电容-10V-33NF-+/-10%-X7R-0402; %208%%161%%192%%224%%195%%251%%179%%198%: SMD陶瓷电容; CODE: 8070598; COMPONENT_HIGH_MAX: 0.55MM; DEVICE: C1005X7R1C333KT000F
C71 C72 = C: %182%%238%%182%%168%%185%%164%%215%%247%%181%%231%%209%%185%(V): 10; %195%%232%%202%%246%: SMD陶瓷电容-10V-2200NF-+/-10%-X5R-0603; %208%%161%%192%%224%%195%%251%%179%%198%: SMD陶瓷电容; CODE: 8070573; COMPONENT_HIGH_MAX: 0.9MM; DEVICE: GRM188R61A225KE34D
C76 C82 C84 = C: %182%%238%%182%%168%%185%%164%%215%%247%%181%%231%%209%%185%(V): 50; %195%%232%%202%%246%: SMD陶瓷电容-50V-0.022NF-+/-5%-NP0-0402-BT; %208%%161%%192%%224%%195%%251%%179%%198%: SMD陶瓷电容; CODE: 8070545; COMPONENT_HIGH_MAX: 0.55MM; DEVICE: RMUMK105CG220JV_F
C83 = C: %182%%238%%182%%168%%185%%164%%215%%247%%181%%231%%209%%185%(V): 50; %195%%232%%202%%246%: SMD陶瓷电容-50V-3.3NF-±10%-X7R-0402; %208%%161%%192%%224%%195%%251%%179%%198%: SMD陶瓷电容; CODE: 8070621; COMPONENT_HIGH_MAX: 0.55MM; DEVICE: GRM155R71H332KA01D
D4 = D_A: %195%%232%%202%%246%: 肖特基二极管-10V-3A-0.24V-SOD323-BT; %208%%161%%192%%224%%195%%251%%179%%198%: 肖特基二极管; CODE: 15010252; COMPONENT_HIGH_MAX: 1.1MM; DEVICE: BAT60BE6327
J1 = PWC3_C: %195%%232%%202%%246%: IO连接器-DC JACK-3PIN-母座-3.9/1.3MM弯式-5V2A-00482858; CODE: 14240410; COMPONENT_HIGH_MAX: 11.25MM; DEVICE: DC_012_HW
J10 = PWC3_C: %195%%232%%202%%246%: IO连接器-DC JACK-3PIN-母座-3.9/1.3MM弯式-5V2A-00482858; CODE: *; COMPONENT_HIGH_MAX: 11.25MM; DEVICE: DC_012_HW
L2-L4 = SWPA4020S3R3MT
L5 = SWPA5040S6R8MT
R4 = R: %182%%238%%182%%168%%185%%166%%194%%202%(W): 0.06; %195%%232%%202%%246%: 片式厚膜电阻器-0.0625W-100000OHM-+/-5%-0402; %208%%161%%192%%224%%195%%251%%179%%198%: 片式厚膜电阻器; %215%%232%%214%%181%%212%%202%%208%%237%%198%%171%%178%%238%: +/-5%; CODE: 7090831; COMPONENT_HIGH_MAX: 0.4MM; DEVICE: RK73B1ELTP104J
R6 = R: %182%%238%%182%%168%%185%%166%%194%%202%(W): 0.06; %195%%232%%202%%246%: 片式厚膜电阻器-0.0625W-47000OHM-+/-5%-0402-ELOM; %208%%161%%192%%224%%195%%251%%179%%198%: 片式厚膜电阻器; %215%%232%%214%%181%%212%%202%%208%%237%%198%%171%%178%%238%: +/-5%; CODE: 7090819; COMPONENT_HIGH_MAX: 0.4MM; DEVICE: RC0402JR_0747K
R7 R105 = R: %182%%238%%182%%168%%185%%166%%194%%202%(W): 0.06; %195%%232%%202%%246%: 片式厚膜电阻器-0.0625W-51000OHM-+/-1%-0402; %208%%161%%192%%224%%195%%251%%179%%198%: 片式厚膜电阻器; %215%%232%%214%%181%%212%%202%%208%%237%%198%%171%%178%%238%: +/-1%; CODE: 7091384; COMPONENT_HIGH_MAX: 0.4MM; DEVICE: RC_02W5102FT
R10 = R: %182%%238%%182%%168%%185%%166%%194%%202%(W): 0.06; %195%%232%%202%%246%: 片式厚膜电阻器-0.0625W-150000OHM-+/-1%-0402; %208%%161%%192%%224%%195%%251%%179%%198%: 片式厚膜电阻器; %215%%232%%214%%181%%212%%202%%208%%237%%198%%171%%178%%238%: +/-1%; CODE: 7090833; COMPONENT_HIGH_MAX: 0.4MM; DEVICE: RK73H1ELTP1503F
R13 = R: %182%%238%%182%%168%%185%%166%%194%%202%(W): 0.1; %195%%232%%202%%246%: 片式厚膜电阻器-0.1W-26100OHM-+/-1%-0603-BT; %208%%161%%192%%224%%195%%251%%179%%198%: 片式厚膜电阻器; %215%%232%%214%%181%%212%%202%%208%%237%%198%%171%%178%%238%: +/-1%; CODE: 7091991; COMPONENT_HIGH_MAX: 0.55MM; DEVICE: RK73H1JTTD2612F
R21 R23 = R: %182%%238%%182%%168%%185%%166%%194%%202%(W): 0.1; %195%%232%%202%%246%: 片式厚膜电阻器-0.1W-1000OHM-+/-1%-0603; %208%%161%%192%%224%%195%%251%%179%%198%: 片式厚膜电阻器; %215%%232%%214%%181%%212%%202%%208%%237%%198%%171%%178%%238%: +/-1%; CODE: 7092250; COMPONENT_HIGH_MAX: 0.5MM; DEVICE: RK73H1JTTD1001F
R35 R73 R81 = R: %182%%238%%182%%168%%185%%166%%194%%202%(W): 0.06; %195%%232%%202%%246%: 片式厚膜电阻器-0.0625W-20000OHM-+/-1%-0402-TS16949; %208%%161%%192%%224%%195%%251%%179%%198%: 片式厚膜电阻器; %215%%232%%214%%181%%212%%202%%208%%237%%198%%171%%178%%238%: +/-1%; CODE: 7091374; COMPONENT_HIGH_MAX: 0.4MM; DEVICE: RC_02W2002FT
R52 R118 = R: %182%%238%%182%%168%%185%%166%%194%%202%(W): 0.06; %195%%232%%202%%246%: 片式厚膜电阻器-0.0625W-100000OHM-+/-5%-0402-BT; %208%%161%%192%%224%%195%%251%%179%%198%: 片式厚膜电阻器; %215%%232%%214%%181%%212%%202%%208%%237%%198%%171%%178%%238%: +/-5%; CODE: 7090831; COMPONENT_HIGH_MAX: 0.4MM; DEVICE: RK73B1ELTP104J
R53 R100 = R: %182%%238%%182%%168%%185%%166%%194%%202%(W): 0.06; %195%%232%%202%%246%: 片式厚膜电阻器-0.0625W-15000OHM-+/-1%-0402-BT; %208%%161%%192%%224%%195%%251%%179%%198%: 片式厚膜电阻器; %215%%232%%214%%181%%212%%202%%208%%237%%198%%171%%178%%238%: +/-1%; CODE: 7091372; COMPONENT_HIGH_MAX: 0.4MM; DEVICE: RC_02W1502FT
R70 = R: %182%%238%%182%%168%%185%%166%%194%%202%(W): 0.06; %195%%232%%202%%246%: 片式厚膜电阻器-0.0625W-33000OHM-+/-5%-0402; %208%%161%%192%%224%%195%%251%%179%%198%: 片式厚膜电阻器; %215%%232%%214%%181%%212%%202%%208%%237%%198%%171%%178%%238%: +/-5%; CODE: 7090828; COMPONENT_HIGH_MAX: 0.4MM; DEVICE: RK73B1ELTP333J
R14 R95 = R: %182%%238%%182%%168%%185%%166%%194%%202%(W): 0.06; %195%%232%%202%%246%: 片式厚膜电阻器-0.0625W-0OHM-< 50MOHM-0402-1A-BT; %208%%161%%192%%224%%195%%251%%179%%198%: 片式厚膜电阻器; %215%%232%%214%%181%%212%%202%%208%%237%%198%%171%%178%%238%: < 50MOHM; CODE: 7090800; DEVICE: RC0402JR_070R
R99 = R: %182%%238%%182%%168%%185%%166%%194%%202%(W): 0.06; %195%%232%%202%%246%: 片式厚膜电阻器-0.0625W-11300OHM-+/-1%-0402; %208%%161%%192%%224%%195%%251%%179%%198%: 片式厚膜电阻器; %215%%232%%214%%181%%212%%202%%208%%237%%198%%171%%178%%238%: +/-1%; CODE: 7090816; COMPONENT_HIGH_MAX: 0.4MM; DEVICE: RC0402FR_0711K3
R101 = R: %182%%238%%182%%168%%185%%166%%194%%202%(W): 0.06; %195%%232%%202%%246%: 片式厚膜电阻器-0.0625W-24000OHM-+/-1%-0402; %208%%161%%192%%224%%195%%251%%179%%198%: 片式厚膜电阻器; %215%%232%%214%%181%%212%%202%%208%%237%%198%%171%%178%%238%: +/-1%; CODE: 7091376; COMPONENT_HIGH_MAX: 0.4MM; DEVICE: RC_02W2402FT
R102 = R: %182%%238%%182%%168%%185%%166%%194%%202%(W): 0.06; %195%%232%%202%%246%: 片式厚膜电阻器-0.0625W-180000OHM-+/-1%-0402; %208%%161%%192%%224%%195%%251%%179%%198%: 片式厚膜电阻器; %215%%232%%214%%181%%212%%202%%208%%237%%198%%171%%178%%238%: +/-1%; CODE: 7090823; COMPONENT_HIGH_MAX: 0.4MM; DEVICE: RC0402FR_07180KL
R104 = R: %182%%238%%182%%168%%185%%166%%194%%202%(W): 0.06; %195%%232%%202%%246%: 片式厚膜电阻器-0.0625W-2200OHM-+/-1%-0402; %208%%161%%192%%224%%195%%251%%179%%198%: 片式厚膜电阻器; %215%%232%%214%%181%%212%%202%%208%%237%%198%%171%%178%%238%: +/-1%; CODE: 7090810; COMPONENT_HIGH_MAX: 0.4MM; DEVICE: RC0402FR_072K2L
R110 = R: %182%%238%%182%%168%%185%%166%%194%%202%(W): 0.06; %195%%232%%202%%246%: 片式厚膜电阻器-0.0625W-75000OHM-+/-1%-0402; %208%%161%%192%%224%%195%%251%%179%%198%: 片式厚膜电阻器; %215%%232%%214%%181%%212%%202%%208%%237%%198%%171%%178%%238%: +/-1%; CODE: 7091008; COMPONENT_HIGH_MAX: 0.4MM; DEVICE: RK73H1ETTD7502F
U11 U13 = SY8032
U14 = MP1484
U15 = SY8009A
C6 = C: %182%%238%%182%%168%%185%%164%%215%%247%%181%%231%%209%%185%(V): 10; %195%%232%%202%%246%: SMD陶瓷电容-10V-220NF-+/-10%-X7R-0603-供电专用-供电专用; %208%%161%%192%%224%%195%%251%%179%%198%: SMD陶瓷电容; CODE: 8070856; COMPONENT_HIGH_MAX: 0.9MM; DEVICE: C0603C224K8RAC7867
Q4 = NPN-BEC: %195%%232%%202%%246%: 三极管-NPN-45V-100MA-225MW-200MV@100MA-SOT-23-180@2MA; %208%%161%%192%%224%%195%%251%%179%%198%: 三极管; CODE: 15050206; COMPONENT_HIGH_MAX: 1.26MM; DEVICE: BC847AE6327
Q13 Q14 = FETP-GSD: %195%%232%%202%%246%: MOSFET-P沟道--8V--3A-50MOHM--8V-SOT23; %208%%161%%192%%224%%195%%251%%179%%198%: MOSFET; CODE: 15060134; COMPONENT_HIGH_MAX: 1.11MM; DEVICE: IRLML6401TR
R98 = R: %182%%238%%182%%168%%185%%166%%194%%202%(W): 0.06; %195%%232%%202%%246%: 片式厚膜电阻器-0.0625W-10000OHM-±5%-0402; %208%%161%%192%%224%%195%%251%%179%%198%: 片式厚膜电阻器; %215%%232%%214%%181%%212%%202%%208%%237%%198%%171%%178%%238%: ±5%; CODE: 7090815; COMPONENT_HIGH_MAX: 0.4MM; DEVICE: RC_02W103JT
R144 = R: %182%%238%%182%%168%%185%%166%%194%%202%(W): 0.06; %195%%232%%202%%246%: 片式厚膜电阻器-0.0625W-4700OHM-+/-5%-0402-BT; %208%%161%%192%%224%%195%%251%%179%%198%: 片式厚膜电阻器; %215%%232%%214%%181%%212%%202%%208%%237%%198%%171%%178%%238%: +/-5%; CODE: 7090793; COMPONENT_HIGH_MAX: 0.4MM; DEVICE: RK73B1ELTP472J
C3 C7 C9 C10 C16 C18 C188 = C: %182%%238%%182%%168%%185%%164%%215%%247%%181%%231%%209%%185%(V): 25; %195%%232%%202%%246%: SMD陶瓷电容-25V-1000NF-+/-10%-X7R-0603; %208%%161%%192%%224%%195%%251%%179%%198%: SMD陶瓷电容; CODE: 8070962; COMPONENT_HIGH_MAX: 0.9MM; DEVICE: CETMK107B7105KA_T
C22 C248 C250 = C: %182%%238%%182%%168%%185%%164%%215%%247%%181%%231%%209%%185%(V): 6.3; %195%%232%%202%%246%: SMD陶瓷电容-6.3V-2200NF-+/-20%-X5R-0402-TS16949; %208%%161%%192%%224%%195%%251%%179%%198%: SMD陶瓷电容; CODE: 8070667; COMPONENT_HIGH_MAX: 0.6MM; DEVICE: GRM155R60J225ME15D
C42 C48 C49 C57 C66 C74 C78 C85-C87 C89 C194 C201-C206 C208-C216 C218-C221 C223-C240 C258 C271 C308 = C: %182%%238%%182%%168%%185%%164%%215%%247%%181%%231%%209%%185%(V): 10; %195%%232%%202%%246%: SMD陶瓷电容-10V-100NF-+/-10%-X5R-0402; %208%%161%%192%%224%%195%%251%%179%%198%: SMD陶瓷电容; CODE: 8070561; COMPONENT_HIGH_MAX: 0.55MM; DEVICE: C0402C104K8PAC_7867
C364 C365 = C: %182%%238%%182%%168%%185%%164%%215%%247%%181%%231%%209%%185%(V): 50; %195%%232%%202%%246%: SMD陶瓷电容-50V-0.03NF-+/-5%-NPO-0402; %208%%161%%192%%224%%195%%251%%179%%198%: SMD陶瓷电容; CODE: 8070604; COMPONENT_HIGH_MAX: 0.55MM; DEVICE: GRM1555C1H300J
LB1 LB8 LB11 LB18 LB20 LB31 LB35 = R: %182%%238%%182%%168%%185%%166%%194%%202%(W): 0.06; %195%%232%%202%%246%: 片式厚膜电阻器-0.0625W-0OHM-< 50MOHM-0402-1A-BT; %208%%161%%192%%224%%195%%251%%179%%198%: 片式厚膜电阻器; %215%%232%%214%%181%%212%%202%%208%%237%%198%%171%%178%%238%: < 50MOHM; CODE: 7090800; COMPONENT_HIGH_MAX: 0.4MM; DEVICE: RC0402JR_070R
LB14 LB17 = R: %182%%238%%182%%168%%185%%166%%194%%202%(W): 0.06; %195%%232%%202%%246%: 片式厚膜电阻器-0.0625W-0OHM-< 56MOHM-0402-1A-BT; %208%%161%%192%%224%%195%%251%%179%%198%: 片式厚膜电阻器; %215%%232%%214%%181%%212%%202%%208%%237%%198%%171%%178%%238%: < 50MOHM; CODE: 7090800; COMPONENT_HIGH_MAX: 0.4MM; DEVICE: RC0402JR_070R
R1 = R: %182%%238%%182%%168%%185%%166%%194%%202%(W): 0.1; %195%%232%%202%%246%: 片式厚膜电阻器-0.1W-1000000OHM-±5%-0603; %208%%161%%192%%224%%195%%251%%179%%198%: 片式厚膜电阻器; %215%%232%%214%%181%%212%%202%%208%%237%%198%%171%%178%%238%: ±5%; CODE: 7090263; DEVICE: RC0603JR_071M
R5 R65 = R: %182%%238%%182%%168%%185%%166%%194%%202%(W): 0.06; %195%%232%%202%%246%: 片式厚膜电阻器-0.0625W-22OHM-+/-5%-0402-BT; %208%%161%%192%%224%%195%%251%%179%%198%: 片式厚膜电阻器; %215%%232%%214%%181%%212%%202%%208%%237%%198%%171%%178%%238%: +/-5%; CODE: 7090803; COMPONENT_HIGH_MAX: 0.4MM; DEVICE: RC0402JR_0722RL
R25 R56 = R: %182%%238%%182%%168%%185%%166%%194%%202%(W): 0.06; %195%%232%%202%%246%: 片式厚膜电阻器-0.0625W-10000OHM-+/-5%-0402-BT; %208%%161%%192%%224%%195%%251%%179%%198%: 片式厚膜电阻器; %215%%232%%214%%181%%212%%202%%208%%237%%198%%171%%178%%238%: +/-5%; CODE: 7090815; DEVICE: RC_02W103JT
R18 R43 R85 R87 = R: %182%%238%%182%%168%%185%%166%%194%%202%(W): 0.06; %195%%232%%202%%246%: 片式厚膜电阻器-0.0625W-270OHM-+/-5%-0402; %208%%161%%192%%224%%195%%251%%179%%198%: 片式厚膜电阻器; %215%%232%%214%%181%%212%%202%%208%%237%%198%%171%%178%%238%: +/-5%; CODE: 7090609; COMPONENT_HIGH_MAX: 0.4MM; DEVICE: RC0402JR_07270R
R61 = R: %182%%238%%182%%168%%185%%166%%194%%202%(W): 0.06; %195%%232%%202%%246%: 片式薄膜电阻器-0.0625W-200OHM-+/-0.1%-0402-+/-50PPM/DEGC; %208%%161%%192%%224%%195%%251%%179%%198%: 片式薄膜电阻器; %215%%232%%214%%181%%212%%202%%208%%237%%198%%171%%178%%238%: +/-0.1%; CODE: 7110054; COMPONENT_HIGH_MAX: 0.4MM; DEVICE: RN731ETTP2000B50
R82 R83 = R: %182%%238%%182%%168%%185%%166%%194%%202%(W): 0.06; %195%%232%%202%%246%: 片式厚膜电阻器-0.0625W-10000OHM-+/-5%-0402-BT; %208%%161%%192%%224%%195%%251%%179%%198%: 片式厚膜电阻器; %215%%232%%214%%181%%212%%202%%208%%237%%198%%171%%178%%238%: +/-5%; CODE: 7090815; COMPONENT_HIGH_MAX: 0.4MM; DEVICE: RC_02W103JT
R40 R47 R88 = R: %182%%238%%182%%168%%185%%166%%194%%202%(W): 0.06; %195%%232%%202%%246%: 片式厚膜电阻器-0.0625W-1000OHM-+/-5%-0402-BT; %208%%161%%192%%224%%195%%251%%179%%198%: 片式厚膜电阻器; %215%%232%%214%%181%%212%%202%%208%%237%%198%%171%%178%%238%: +/-5%; CODE: 7090809; COMPONENT_HIGH_MAX: 0.4MM; DEVICE: RC0402JR_071KL
R44 R51 R173 = R: %182%%238%%182%%168%%185%%166%%194%%202%(W): 0.06; %195%%232%%202%%246%: 片式厚膜电阻器-0.0625W-10000OHM-+/-1%-0402-BT; %208%%161%%192%%224%%195%%251%%179%%198%: 片式厚膜电阻器; %215%%232%%214%%181%%212%%202%%208%%237%%198%%171%%178%%238%: +/-1%; CODE: 7090867; COMPONENT_HIGH_MAX: 0.4MM; DEVICE: RK73H1ETTP1002F
X2 = X_B: %195%%232%%202%%246%: 晶体谐振器-24MHZ; %208%%161%%192%%224%%195%%251%%179%%198%: 晶体谐振器; CODE: 12020151; COMPONENT_HIGH_MAX: 1MM; DEVICE: E5SB400000F15D11
C15 C334 = C: %182%%238%%182%%168%%185%%164%%215%%247%%181%%231%%209%%185%(V): 10; %195%%232%%202%%246%: SMD陶瓷电容-10V-1000NF-+/-10%-X5R-0402-BT,TS16949; %208%%161%%192%%224%%195%%251%%179%%198%: SMD陶瓷电容; CODE: 8070612; COMPONENT_HIGH_MAX: 0.55MM; DEVICE: CV05X5R105K10AH
C164 C182 C336 = C: %182%%238%%182%%168%%185%%164%%215%%247%%181%%231%%209%%185%(V): 16; %195%%232%%202%%246%: SMD陶瓷电容-16V-10NF-+/-10%-X7R-0402-BT,TS16949; %208%%161%%192%%224%%195%%251%%179%%198%: SMD陶瓷电容; CODE: 8070449; COMPONENT_HIGH_MAX: 0.55MM; DEVICE: GRM155R71C103KA01D
C251 = C: %182%%238%%182%%168%%185%%164%%215%%247%%181%%231%%209%%185%(V): 6.3; %195%%232%%202%%246%: SMD陶瓷电容-6.3V-2200NF-+/-10%-X5R-0603-BT; %208%%161%%192%%224%%195%%251%%179%%198%: SMD陶瓷电容; CODE: 8070563; COMPONENT_HIGH_MAX: 0.95MM; DEVICE: CM105X5R225K06AT
LB12 = LB_v2: %195%%232%%202%%246%: EMI磁珠-+/-25%-1000OHM-1.25OHM-0.25A-0402-1400OHM@1GHZ; %208%%161%%192%%224%%195%%251%%179%%198%: EMI磁珠; CODE: 10070019; COMPONENT_HIGH_MAX: 0.65MM; DEVICE: BLM15HG102SN1D
R32 = R: %182%%238%%182%%168%%185%%166%%194%%202%(W): 0.06; %195%%232%%202%%246%: 片式厚膜电阻器-0.0625W-12000OHM-+/-1%-0402; %208%%161%%192%%224%%195%%251%%179%%198%: 片式厚膜电阻器; %215%%232%%214%%181%%212%%202%%208%%237%%198%%171%%178%%238%: +/-1%; CODE: 7090817; DEVICE: RC0402FR_0712K
S1 = PSW4_A: CODE: 16100051
S2 = MSW-6A: %195%%232%%202%%246%: 微动开关-SPST-12VDC-0.05A-贴片-0.5MM-5.2*5.2*1.5MM-1,000,000; %208%%161%%192%%224%%195%%251%%179%%198%: 微动开关; COMPONENT_HIGH_MAX: 1.71MM; DEVICE: TMG_533_T_R
U1 = Hi3798MV100: DEVICE: HI3798MV100_A
C313 C314 = C: %182%%238%%182%%168%%185%%164%%215%%247%%181%%231%%209%%185%(V): 50; %195%%232%%202%%246%: SMD陶瓷电容-50V-1NF-+/-10%-X7R-0402-BT; %208%%161%%192%%224%%195%%251%%179%%198%: SMD陶瓷电容; CODE: 8070531; COMPONENT_HIGH_MAX: 0.56MM; DEVICE: 04025C102KAT2A
C315 C319 = C: %182%%238%%182%%168%%185%%164%%215%%247%%181%%231%%209%%185%(V): 6.3; %195%%232%%202%%246%: SMD陶瓷电容-6.3V-10000NF-+/-10%-X5R-0805-TS16949; %208%%161%%192%%224%%195%%251%%179%%198%: SMD陶瓷电容; CODE: 8070565; COMPONENT_HIGH_MAX: 1.45MM; DEVICE: CEJMK212BJ106KD_T
R16 R17 = R: %195%%232%%202%%246%: 片式厚膜电阻器-0.0625W-100OHM-±5%-0402; CODE: 07090863; COMPONENT_HIGH_MAX: 0.4MM; DEVICE: RC0402JR_07100R
R33 R54 R55 R75 R78 R84 R92 R93 = R: %182%%238%%182%%168%%185%%166%%194%%202%(W): 0.06; %195%%232%%202%%246%: 片式厚膜电阻器-0.0625W-1000OHM-+/-1%-0402-BT; %208%%161%%192%%224%%195%%251%%179%%198%: 片式厚膜电阻器; %215%%232%%214%%181%%212%%202%%208%%237%%198%%171%%178%%238%: +/-1%; CODE: 7091282; COMPONENT_HIGH_MAX: 0.4MM; DEVICE: RC0402FR_071KL
R46 R71 = R: %182%%238%%182%%168%%185%%166%%194%%202%(W): 0.06; %195%%232%%202%%246%: 片式厚膜电阻器-0.0625W-240OHM-+/- 1%-0402-BT; %208%%161%%192%%224%%195%%251%%179%%198%: 片式厚膜电阻器; %215%%232%%214%%181%%212%%202%%208%%237%%198%%171%%178%%238%: +/- 1%; CODE: 7091782; COMPONENT_HIGH_MAX: 0.4MM; DEVICE: RC0402FR_07240RL
U3 U6 = MT41J256M16RE-15E-D_0: %195%%232%%202%%246%: DDR3 DRAM-4GBIT-800MHZ-16BIT-1.5V-FBGA96(无铅); %208%%161%%192%%224%%195%%251%%179%%198%: DDR3 DRAM; CODE: 40020173; COMPONENT_HIGH_MAX: -99999999MM

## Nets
1V1_CORE: C34.1(A) C37.1(A) C51.1(A) C82.2(B) C90.1(A) L3.2(B) LB11.1(A) LB12.2 LB31.1(A) R101.2(B) ; also on sheet 11
1V1_CPU: C28.1 C35.1(A) C41.1(A) C76.2(B) C116.1(A) L2.2(B) R53.2(B) ; also on sheet 11
1V5_DDR3: C40.1(A) C49.1(A) C66.1(A) C68.1(A) C84.2(B) C110.1(A) C201.1(A) C202.1(A) C203.1(A) C204.1(A) C205.1(A) C206.1(A) C208.1(A) C209.1(A) C210.1(A) C211.1(A) C212.1(A) C213.1(A) C214.1(A) C215.1(A) C216.1(A) C218.1(A) C219.1(A) C220.1(A) C221.1(A) C223.1(A) C224.1(A) C225.1(A) C226.1(A) C227.1(A) C228.1(A) C229.1(A) C230.1(A) C231.1(A) C232.1(A) C233.1(A) C234.1(A) C235.1(A) C236.1(A) C237.1(A) C238.1(A) C239.1(A) C240.1(A) C258.1(A) C315.1(A) C319.1(A) L4.2(B) R10.2(B) R33.1(A) R54.1(A) R78.1(A) R92.1(A) U3.A1(VDDQ1) U3.A8(VDDQ2) U3.B2(VDD1) U3.C1(VDDQ3) U3.C9(VDDQ4) U3.D2(VDDQ5) U3.D9(VDD2) U3.E9(VDDQ6) U3.F1(VDDQ7) U3.G7(VDD3) U3.H2(VDDQ8) U3.H9(VDDQ9) U3.K2(VDD4) U3.K8(VDD5) U3.N1(VDD6) U3.N9(VDD7) U3.R1(VDD8) U3.R9(VDD9) U6.A1(VDDQ1) U6.A8(VDDQ2) U6.B2(VDD1) U6.C1(VDDQ3) U6.C9(VDDQ4) U6.D2(VDDQ5) U6.D9(VDD2) U6.E9(VDDQ6) U6.F1(VDDQ7) U6.G7(VDD3) U6.H2(VDDQ8) U6.H9(VDDQ9) U6.K2(VDD4) U6.K8(VDD5) U6.N1(VDD6) U6.N9(VDD7) U6.R1(VDD8) U6.R9(VDD9) ; also on sheet 10
3V3: C2.1(A) C4.1(A) C25.1(A) C26.1(A) C27.1(A) C39.1(A) C46.1(A) C53.1(A) C67.1(A) C69.1(A) C91.1(A) C114.1(A) L5.2(B) Q13.2(S) R6.1(A) R88.2(B) R105.2(B) U11.4(VIN) U13.4(VIN) U15.4(VIN) ; also on sheet 11 15 17
3V3_MOS: C74.1(A) LB1.2(B) LB8.2(B) LB14.1(A) LB17.2(B) LB18.1(A) LB20.1(A) LB35.1(A) Q13.3(D) R44.2(B) R47.1(A) R83.2(B) U1.M19(DVDD3318_NF_2) U1.N19(DVDD3318_NF_1) ; also on sheet 10 11 13 14 15 17 18 19
5V0: C6.1(A) C58.1 C59.1(A) C111.1(A) C112.1(A) D4.2(A) J1.1(A1) J10.1(A1) Q14.2(S) R4.1(A) R144.1(A) U14.2(IN)
5V0_MOS: Q14.3(D) ; also on sheet 14 16 19
AVDD11_USB3: C16.1(A) C48.1(A) LB11.2(B) U1.R16(DVDD11_USB3) U1.R17(AVDD11_VP_USB3) U1.T17(AVDD11_VPTX0_USB3)
AVDD33_ADAC: C188.1(A) C194.1(A) LB35.2(B) U1.E19(AVDD33_ADAC)
AVDD33_USB2: C3.1(A) LB17.1(A) U1.K19(AVDD33_USB2)
AVDD33_USB3: C18.1(A) LB18.2(B) U1.W17(AVDD33_USB3_1) U1.W18(AVDD33_USB3_2)
GND: C2.2(B) C3.2(B) C4.2(B) C5.2(B) C7.2(B) C8.2(B) C9.2(B) C10.2(B) C15.2(B) C16.2(B) C18.2(B) C22.1(A) C24.2(B) C25.2(B) C26.2(B) C27.2(B) C28.2 C30.2(B) C34.2(B) C35.2(B) C37.2(B) C39.2(B) C40.2(B) C41.2(B) C42.1(A) C43.2(B) C44.2(B) C45.2(B) C46.2(B) C48.2(B) C51.2(B) C53.2(B) C57.2(B) C58.2 C59.2(B) C67.2(B) C68.2(B) C69.2(B) C71.2(B) C72.2(B) C74.2(B) C78.2(B) C85.2(B) C86.2(B) C87.2(B) C89.2(B) C90.2(B) C91.2(B) C110.2(B) C111.2(B) C112.2(B) C114.2(B) C116.2(B) C164.2(B) C182.2(B) C188.2(B) C194.2(B) C201.2(B) C202.2(B) C203.2(B) C204.2(B) C205.2(B) C206.2(B) C209.2(B) C210.2(B) C211.2(B) C212.2(B) C213.2(B) C214.2(B) C215.2(B) C216.2(B) C218.2(B) C219.2(B) C220.2(B) C221.2(B) C224.2(B) C225.2(B) C226.2(B) C227.2(B) C228.2(B) C229.2(B) C230.2(B) C231.2(B) C232.2(B) C233.2(B) C234.2(B) C235.2(B) C236.2(B) C237.2(B) C238.2(B) C239.2(B) C240.2(B) C248.2(B) C250.1(A) C251.2(B) C258.2(B) C271.2(B) C281.2(B) C308.2(B) C313.2(B) C314.2(B) C315.2(B) C319.2(B) C334.2(B) C336.2(B) C364.2(B) C365.2(B) J1.2(A2) J1.3(A3) J3.1 J10.2(A2) J10.3(A3) Q4.2(E) R13.1(A) R18.1(A) R25.1(A) R32.1(A) R43.2(B) R46.1(A) R51.2(B) R52.2(B) R55.2(B) R56.1(A) R61.1(A) R71.1(A) R75.2(B) R82.2(B) R84.2(B) R85.2(B) R87.1(A) R93.2(B) R99.1(A) R100.2(B) R104.2(B) R173.2(B) S1.1 S1.3 S1.4 S2.3 S2.4 S2.5 S2.6 U1.A3(AVSS_FE_4) U1.A23(AVSS_ADAC_5) U1.B3(AVSS_FE_2) U1.B8(AVSS_USB1_2) U1.B23(AVSS_ADAC_4) U1.C4(AVSS_FE_3) U1.C6(AVSS_USB0) U1.C8(AVSS_USB1_1) U1.C15(AVSS_HDMITX_1) U1.C17(AVSS_HDMITX_2) U1.C21(AVSS_ADAC_2) U1.C22(AVSS_ADAC_3) U1.D4(AVSS_FE_1) U1.D6(AVSS_USB2_3) U1.D14(AVSS_HDMITX_5) U1.D15(AVSS_HDMITX_3) U1.D17(AVSS_HDMITX_4) U1.D20(AVSS_ADAC_1) U1.D21(AVSS_VDAC_1) U1.D22(AVSS_VDAC_5) U1.E16(AVSS_HDMITX_7) U1.E17(AVSS_HDMITX_6) U1.E21(AVSS_VDAC_2) U1.E22(AVSS_VDAC_3) U1.F21(AVSS_VDAC_4) U1.G20(AVSS_VDAC_6) U1.L20(AVSS_USB2_1) U1.L21(AVSS_USB2_2) U3.A9(VSS1) U3.B1(VSSQ1) U3.B3(VSS2) U3.B9(VSSQ2) U3.D1(VSSQ3) U3.D8(VSSQ4) U3.E1(VSS3) U3.E2(VSSQ5) U3.E8(VSSQ6) U3.F9(VSSQ7) U3.G1(VSSQ8) U3.G8(VSS4) U3.G9(VSSQ9) U3.J2(VSS5) U3.J8(VSS6) U3.M1(VSS7) U3.M9(VSS8) U3.P1(VSS9) U3.P9(VSS10) U3.T1(VSS11) U3.T9(VSS12) U6.A9(VSS1) U6.B1(VSSQ1) U6.B3(VSS2) U6.B9(VSSQ2) U6.D1(VSSQ3) U6.D8(VSSQ4) U6.E1(VSS3) U6.E2(VSSQ5) U6.E8(VSSQ6) U6.F9(VSSQ7) U6.G1(VSSQ8) U6.G8(VSS4) U6.G9(VSSQ9) U6.J2(VSS5) U6.J8(VSS6) U6.M1(VSS7) U6.M9(VSS8) U6.P1(VSS9) U6.P9(VSS10) U6.T1(VSS11) U6.T9(VSS12) U11.2(GND) U13.2(GND) U14.4(GND1) U14.9(GND2) U15.2(GND) X2.2(GND1) X2.4(GND2) ; also on sheet 10 11 12 13 14 15 16 17 18 19
ADAC_VOUTL: U1.B22(ADAC_VOUTL) ; also on sheet 16
ADAC_VOUTR: U1.A22(ADAC_VOUTR) ; also on sheet 16
CORE_CTRL: R23.2(B) U1.H22(GPIO2_6/I2C2_SCL/PMC_PWM0)
CPU_CTRL: R21.2(B) U1.H23(GPIO2_7/I2C2_SDA/PMC_PWM1)
CVBS: U1.E23(VDAC) ; also on sheet 18
DDR_ADDR0: U3.N3(A0) U6.N3(A0) ; also on sheet 10
DDR_ADDR1: U3.P7(A1) U6.P7(A1) ; also on sheet 10
DDR_ADDR2: U3.P3(A2) U6.P3(A2) ; also on sheet 10
DDR_ADDR3: U3.N2(A3) U6.N2(A3) ; also on sheet 10
DDR_ADDR4: U3.P8(A4) U6.P8(A4) ; also on sheet 10
DDR_ADDR5: U3.P2(A5) U6.P2(A5) ; also on sheet 10
DDR_ADDR6: U3.R8(A6) U6.R8(A6) ; also on sheet 10
DDR_ADDR7: U3.R2(A7) U6.R2(A7) ; also on sheet 10
DDR_ADDR8: U3.T8(A8) U6.T8(A8) ; also on sheet 10
DDR_ADDR9: U3.R3(A9) U6.R3(A9) ; also on sheet 10
DDR_ADDR10: U3.L7(A10/AP) U6.L7(A10/AP) ; also on sheet 10
DDR_ADDR11: U3.R7(A11) U6.R7(A11) ; also on sheet 10
DDR_ADDR12: U3.N7(A12/BC~) U6.N7(A12/BC~) ; also on sheet 10
DDR_ADDR13: U3.T3(A13) U6.T3(A13) ; also on sheet 10
DDR_ADDR14: U3.T7(A14) U6.T7(A14) ; also on sheet 10
DDR_ADDR15: U3.M7(NC5) U6.M7(NC5) ; also on sheet 10
DDR_BA0: U3.M2(BA0) U6.M2(BA0) ; also on sheet 10
DDR_BA1: U3.N8(BA1) U6.N8(BA1) ; also on sheet 10
DDR_BA2: U3.M3(BA2) U6.M3(BA2) ; also on sheet 10
DDR_CASN: U3.K3(~{CAS}) U6.K3(~{CAS}) ; also on sheet 10
DDR_CKE: U3.K9(CKE) U6.K9(CKE) ; also on sheet 10
DDR_CLK1N: R16.2(B) R17.2(B) U3.K7(~{CK}) U6.K7(~{CK}) ; also on sheet 10
DDR_CLK1P: R16.1(A) R17.1(A) U3.J7(CK) U6.J7(CK) ; also on sheet 10
DDR_CSN: U3.L2(~{CS}) U6.L2(~{CS}) ; also on sheet 10
DDR_DM0: U3.E7(LDM) ; also on sheet 10
DDR_DM1: U3.D3(UDM) ; also on sheet 10
DDR_DM2: U6.E7(LDM) ; also on sheet 10
DDR_DM3: U6.D3(UDM) ; also on sheet 10
DDR_DQ0: U3.E3(DQ0) ; also on sheet 10
DDR_DQ1: U3.F7(DQ1) ; also on sheet 10
DDR_DQ2: U3.F2(DQ2) ; also on sheet 10
DDR_DQ3: U3.F8(DQ3) ; also on sheet 10
DDR_DQ4: U3.H3(DQ4) ; also on sheet 10
DDR_DQ5: U3.H8(DQ5) ; also on sheet 10
DDR_DQ6: U3.G2(DQ6) ; also on sheet 10
DDR_DQ7: U3.H7(DQ7) ; also on sheet 10
DDR_DQ8: U3.D7(DQ8) ; also on sheet 10
DDR_DQ9: U3.C3(DQ9) ; also on sheet 10
DDR_DQ10: U3.C8(DQ10) ; also on sheet 10
DDR_DQ11: U3.C2(DQ11) ; also on sheet 10
DDR_DQ12: U3.A7(DQ12) ; also on sheet 10
DDR_DQ13: U3.A2(DQ13) ; also on sheet 10
DDR_DQ14: U3.B8(DQ14) ; also on sheet 10
DDR_DQ15: U3.A3(DQ15) ; also on sheet 10
DDR_DQ16: U6.E3(DQ0) ; also on sheet 10
DDR_DQ17: U6.F7(DQ1) ; also on sheet 10
DDR_DQ18: U6.F2(DQ2) ; also on sheet 10
DDR_DQ19: U6.F8(DQ3) ; also on sheet 10
DDR_DQ20: U6.H3(DQ4) ; also on sheet 10
DDR_DQ21: U6.H8(DQ5) ; also on sheet 10
DDR_DQ22: U6.G2(DQ6) ; also on sheet 10
DDR_DQ23: U6.H7(DQ7) ; also on sheet 10
DDR_DQ24: U6.D7(DQ8) ; also on sheet 10
DDR_DQ25: U6.C3(DQ9) ; also on sheet 10
DDR_DQ26: U6.C8(DQ10) ; also on sheet 10
DDR_DQ27: U6.C2(DQ11) ; also on sheet 10
DDR_DQ28: U6.A7(DQ12) ; also on sheet 10
DDR_DQ29: U6.A2(DQ13) ; also on sheet 10
DDR_DQ30: U6.B8(DQ14) ; also on sheet 10
DDR_DQ31: U6.A3(DQ15) ; also on sheet 10
DDR_DQS0N: U3.G3(~{LDQS}) ; also on sheet 10
DDR_DQS0P: U3.F3(LDQS) ; also on sheet 10
DDR_DQS1N: U3.B7(~{UDQS}) ; also on sheet 10
DDR_DQS1P: U3.C7(UDQS) ; also on sheet 10
DDR_DQS2N: U6.G3(~{LDQS}) ; also on sheet 10
DDR_DQS2P: U6.F3(LDQS) ; also on sheet 10
DDR_DQS3N: U6.B7(~{UDQS}) ; also on sheet 10
DDR_DQS3P: U6.C7(UDQS) ; also on sheet 10
DDR_ODT: U3.K1(ODT) U6.K1(ODT) ; also on sheet 10
DDR_RASN: U3.J3(~{RAS}) U6.J3(~{RAS}) ; also on sheet 10
DDR_RESETN: C313.1(A) C314.1(A) U3.T2(~{RESET}) U6.T2(~{RESET}) ; also on sheet 10
DDR_VREF_A_CA: C49.2(B) C86.1(A) R33.2(B) R55.1(A) U3.M8(VREFCA)
DDR_VREF_A_DQ: C208.2(B) C271.1(A) R54.2(B) R75.1(A) U3.H1(VREFDQ)
DDR_VREF_B_CA: C66.2(B) C87.1(A) R92.2(B) R93.1(A) U6.M8(VREFCA)
DDR_VREF_B_DQ: C223.2(B) C308.1(A) R78.2(B) R84.1(A) U6.H1(VREFDQ)
DDR_WEN: U3.L3(~{WE}) U6.L3(~{WE}) ; also on sheet 10
FE_1V1: C248.1(A) U1.G10(AVDD11_FE)
FE_3V3: C7.1(A) LB8.1(A) U1.E5(AVDD33_FE)
HDMI_TX0N: U1.D16(HDMI_TX0N) ; also on sheet 19
HDMI_TX0P: U1.C16(HDMI_TX0P) ; also on sheet 19
HDMI_TX1N: U1.B15(HDMI_TX1N) ; also on sheet 19
HDMI_TX1P: U1.A15(HDMI_TX1P) ; also on sheet 19
HDMI_TX2N: U1.C14(HDMI_TX2N) ; also on sheet 19
HDMI_TX2P: U1.B14(HDMI_TX2P) ; also on sheet 19
HDMI_TX_1V1: C78.1(A) C164.1(A) C251.1(A) C281.1(A) LB12.1 U1.G14(AVCC11_HDMITX_1) U1.G15(AVCC11_HDMITX_2)
HDMI_TX_3V3: C15.1(A) C57.1(A) LB1.1(A) U1.E15(AVCC33_HDMITX)
HDMI_TX_CEC: U1.C18(GPIO4_7/HDMITX_CEC) ; also on sheet 19
HDMI_TX_HOTPLUG: U1.B19(GPIO4_6/HDMITX_HOTPLUG) ; also on sheet 19
HDMI_TX_SCL: U1.D18(GPIO4_5/HDMITX_SCL) ; also on sheet 19
HDMI_TX_SDA: U1.A19(GPIO4_4/HDMITX_SDA) ; also on sheet 19
HDMI_TXCN: U1.B17(HDMI_TXCN) ; also on sheet 19
HDMI_TXCP: U1.A17(HDMI_TXCP) ; also on sheet 19
IR_IN: U1.Y21(GPIO5_1/IR_IN) ; also on sheet 15
LED0_BASE: U1.B2(GPIO2_2/FE_LED_BASE) ; also on sheet 17
LED0_LINK_ACT: U1.B1(GPIO2_1/FE_LED_ACT) ; also on sheet 17
LED_GREEN: U1.AB22(GPIO5_5/LED_DATA) ; also on sheet 15
LED_RED: U1.AC22(GPIO5_6/LED_CLK) ; also on sheet 15
MUTE_CTRL: U1.C19(MUTE_CTRL/GPIO4_3) ; also on sheet 16
NF_ALE_EMMC_PWREN: U1.N20(NF_ALE/SDIO1_CARD_POWER_EN/GPIO0_1) ; also on sheet 13
NF_CLE: U1.N21(NF_CLE/SDIO1_CWPR/GPIO0_2) ; also on sheet 13
NF_CSN0_EMMC_CMD: U1.N22(NF_CSN0/SDIO1_CCMD) ; also on sheet 13
NF_DQ0_EMMC_D0: U1.R23(EBI_DQ0/SDIO1_CDATA0) ; also on sheet 13
NF_DQ1_EMMC_D1: U1.R22(EBI_DQ1/SDIO1_CDATA1) ; also on sheet 13
NF_DQ2_EMMC_D2: U1.R21(EBI_DQ2/SDIO1_CDATA2) ; also on sheet 13
NF_DQ3_EMMC_D3: U1.T21(EBI_DQ3/SDIO1_CDATA3) ; also on sheet 13
NF_DQ4_EMMC_D4: U1.T20(EBI_DQ4/SDIO1_CDATA4) ; also on sheet 13
NF_DQ5_EMMC_D5: U1.U22(EBI_DQ5/SDIO1_CDATA5) ; also on sheet 13
NF_DQ6_EMMC_D6: U1.U23(EBI_DQ6/SDIO1_CDATA6) ; also on sheet 13
NF_DQ7_EMMC_D7_BOOT_SEL0: R82.1(A) U1.U21(EBI_DQ7/SDIO1_CDATA7/BOOT_SEL0) ; also on sheet 13
NF_RDY0_EMMC_RST: U1.M21(NF_RDY0/SDIO1_RST) ; also on sheet 13
NF_REN_EMMC_CLK: R65.1(A) ; also on sheet 13
NF_WEN_EMMC_DET: R56.2(B) U1.P21(NF_WEN/SDIO1_CARD_DETECT/GPIO0_0) ; also on sheet 13
PWR_OFF/ON: R44.1(A) R51.1(A) U1.J23(JTAG_TDI/GPIO0_7)
RECOVERY: C42.2(B) R47.2(B) S1.2 U1.J22(JTAG_TDO/GPIO2_0)
RX+_PHY0: U1.D5(FE_RXP) ; also on sheet 17
RX-_PHY0: U1.C5(FE_RXN) ; also on sheet 17
SDIO0_CARD_DETECT: U1.F1(SDIO0_CARD_DETECT/GPIO3_6) ; also on sheet 15
SDIO0_CCLK_OUT: R5.1(A) ; also on sheet 15
SDIO0_CCMD: U1.E2(SDIO0_CCMD/GPIO3_3) ; also on sheet 15
SDIO0_CDATA0: U1.D3(SDIO0_CDATA0/GPIO3_1) ; also on sheet 15
SDIO0_CDATA1: U1.C2(SDIO0_CDATA1/GPIO3_0) ; also on sheet 15
SDIO0_CDATA2: U1.F2(SDIO0_CDATA2/GPIO3_5) ; also on sheet 15
SDIO0_CDATA3: U1.E1(SDIO0_CDATA3/GPIO3_4) ; also on sheet 15
SDIO0_CWPR: R25.2(B) U1.C1(SDIO0_CWPR/GPIO2_3)
SDIO0_PWREN: U1.F3(SDIO0_CARD_POWER_EN/GPIO3_7) ; also on sheet 15
SDIO_3318: C22.2(B) U1.G5(CAPACITOR_LDO) ; also on sheet 15
SPDIF_OUT_BOOT_SEL1: R83.1(A) U1.A20(SPDIF_OUT/GPIO4_2/BOOT_SEL1)
STANDBY_PWROFF: R35.1(A) R73.1(A) R81.1(A) R88.1(A) R98.1(A) U1.AB23(GPIO5_0/STANDBY_PWROFF)
TX+_PHY0: U1.B4(FE_TXP) ; also on sheet 17
TX-_PHY0: U1.A4(FE_TXN) ; also on sheet 17
UART0_RXD: U1.AA22(UART0_RXD/UART1_RXD) ; also on sheet 17
UART0_TXD: U1.AA23(UART0_TXD/UART1_TXD) ; also on sheet 17
USB0_DM: U1.A6(USB0_DM) ; also on sheet 14
USB0_DP: U1.B6(USB0_DP) ; also on sheet 14
USB01_1V1: C334.1(A) C336.1(A) LB31.2(B) U1.G11(AVCC11_USB01)
USB01_3V3: C10.1(A) C182.1(A) LB20.2(B) U1.D7(AVDD33_USB01)
USB1_DM: U1.B7(USB1_DM) ; also on sheet 14
USB1_DP: U1.C7(USB1_DP) ; also on sheet 14
USB3_DM: U1.AC18(USB3_DM) ; also on sheet 14
USB3_DP: U1.AB18(USB3_DP) ; also on sheet 14
USB3_RXN: U1.AB20(USB3_RXN) ; also on sheet 14
USB3_RXP: U1.AC20(USB3_RXP) ; also on sheet 14
USB3_TXN: U1.AA19(USB3_TXN) ; also on sheet 14
USB3_TXP: U1.Y19(USB3_TXP) ; also on sheet 14
USB_BOOT: C89.1(A) R40.1(A) S2.1 S2.2
VDAC_3V3: C9.1(A) C85.1(A) LB14.2(B) U1.E20(AVDD33_VDAC_1) U1.F19(AVDD33_VDAC_2) U1.G19(AVDD33_VDAC_3)
XIN: C364.1(A) R1.2(B) U1.W23(XIN) X2.1
XOUT: R1.1(A) R14.1(A) U1.W22(XOUT)
N15113: R40.2(B) U1.H21(USB_BOOT/GPIO2_5)
N15129: R18.2(B) R87.2(B) U1.D8(USB01_REXT)
N15209: C250.2(B) U1.G17(ADAC_VREFDAC)
N15247: R32.2(B) U1.F20(VDAC_IREF)
N16433: C365.1(A) R14.2(B) X2.3
N16479: R173.1(A) U1.E6(FE_REXT)
N16487: R5.2(B) U1.E3(SDIO0_CCLK_OUT/GPIO3_2)
N16539: R61.2(B) U1.Y17(USB3_REXT)
N16543: R43.1(A) R85.1(A) U1.L19(USB2_REXT)
N16983: Q4.1(B) R98.2(B)
N17019: Q4.3(C) R118.2(B) R144.2(B)
N17029: C6.2(B) Q13.1(G) Q14.1(G) R118.1(A)
N18273: R7.1(A) R70.2(B)
N18277: C76.1(A) R53.1(A) R70.1(A) R99.2(B) U11.6(FB)
N18297: C5.1(A) R81.2(B) U13.1(EN)
N18307: C82.1(A) R13.2(B) R101.1(A) R110.1(A) U13.6(FB)
N18327: C8.1(A) R73.2(B) U11.1(EN)
N18337: L4.1(A) U15.3(LX)
N18341: C84.1(A) R10.1(A) R52.1(A) U15.5(FB)
N18409: L3.1(A) U13.3(LX)
N18413: R102.1(A) R110.2(B)
N18417: C45.1(A) C72.1(A) R23.1(A) R102.2(B)
N18429: L2.1(A) U11.3(LX)
N18433: C43.1(A) C71.1(A) R7.2(B) R21.1(A)
N18445: C65.2(B) L5.1(A) U14.3(SW)
N18455: C65.1(A) R95.2(B)
N18459: C44.1(A) U14.8(SS)
N18465: R4.2(B) U14.7(EN)
N18471: C24.1(A) C83.1(A) U14.6(COMP/NC)
N18481: C83.2(B) R104.1(A)
N18485: D4.1(K) R95.1(A) U14.1(BS)
N18491: R100.1(A) R105.1(A) U14.5(FB)
N18531: C30.1(A) R6.2(B) R35.2(B) U15.1(EN)
N4379666: R46.2(B) U3.L8(ZQ)
N4391010: R71.2(B) U6.L8(ZQ)
N16949616: R65.2(B) U1.N23(NF_REN/SDIO1_CCLK_OUT)

Not connected (* = marked no-connect by the designer): ID1 1*; ID2 1*; ID3 1*; ID4 1*; ID5 1*; ID6 1*; M20 1(GND)*; M21 1(GND)*; M22 1(GND)*; M23 1(GND)*; U1 A8(GPIO6_7/I2S0_DIN0) A9(GPIO6_5/I2S0_DOUT0) A11(GPIO6_1/SPI_CSN1) A12(GPIO4_1/I2C1_SCL/UART2_TXD/SPI_SDI) AA21(GPIO5_2/LED_CSN0) B9(GPIO6_6/I2S0_MCLK) B11(GPIO6_0/I2C1_SDA/UART2_RTSN/SPI_CSN0) B12(GPIO4_0/UART2_RXD/SPI_SDO) C9(GPIO6_4/I2S0_WS) C10(GPIO6_3/I2S0_BCLK) C11(GPIO6_2/SLIC_RST) C12(GPIO0_3/UART2_CTSN/SPI_SCLK) G21(JTAG_SEL) J21(JTAG_TCK/GPIO0_6) K20(JTAG_TRSTN/GPIO0_5) K21(JTAG_TMS/GPIO0_4) L22(USB2_DM) L23(USB2_DP) Y22(FUNC_SEL); U3 J1(NC1)* J9(NC2)* L1(NC3)* L9(NC4)*; U6 J1(NC1)* J9(NC2)* L1(NC3)* L9(NC4)*; U11 5(PG)*; U13 5(PG)*

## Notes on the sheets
sheet 1
- DDRB
- 1%
- 1%
- 1%
- 1%
- 1%
- 1%
sheet 2
- DDRA
- 1%
- 1%
- 1%
- 1%
- 1%
- 1%
sheet 3
- PAGE1
- Title Page
- PAGE2
- Power Tree
- PAGE3
- Block Diagram
- PAGE4
- Power on board
- PAGE5
- Power Ctrl
- PAGE6
- Unit 1 of Hi3798M(NAND/USB3.0/IR/SDIO/XTAL/FE)
- PAGE7
- Unit 2 of Hi3798M(JTAG/USB2.0/HDMI TX/DAC/I2S/SPI/UART)
- PAGE8
- Unit 3 of Hi3798M(DDR3)
- PAGE9
- Unit 4 of Hi3798M(POWER)
- PAGE10
- Unit 5 of Hi3798M(VSS)
- Hi3798MDMO1A
- PAGE11
- DDRA
- PAGE12
- DDRB
- PAGE13
- NAND FLASH/EMMC
- PAGE14
- USB2.0/USB3.0/WIFI
- VER_E_V1.0.0.0
- PAGE15
- SD CARD/IR
- PAGE16
- Audio Output
- PAGE17
- FE PHY/UART
- PAGE18
- VDAC OUTPUT
- Hi3798MV100 DEMO Board
- PAGE19
- HDMI TX
- 4 layers PCB with 2 DDR3 16bit
- Board Size:86mm x 88mm x 1.6mm
sheet 4
- Power Tree
- 5V0_MOS
- AUDIO AMP
- PMOS
- 1000mA
- HDMI
- SPDIF
- 5V
- USB x 2
- SW x 2
- 5V_VBUS
- 3V3
- MAX 2600mA
- 20mA
- 3V3 Standby
- DCDC
- IR & LED
- PMOS
- 3V3_MOS
- 170mA
- CHIP
- I/O
- SD CARD
- USB
- VDAC
- NAND FLASH/eMMC
- ADAC
- FE
- HDMI
- 1V1_CORE
- PLL
- 612mA(MAX 2300mA)
- DCDC
- CORE
- USB
- VDAC
- 1V1_CPU
- CPU
- HDMI
- DCDC
- 303mA(MAX 2560mA)
- FE
- PLL
- 1V5_DDR3
- DCDC
- DDR PHY
- 421mA(MAX 1000mA)
- DDR
sheet 5
- Block Diagram
- ETH
- HDMI
- AV
- KEY
- 5V0
- WiFi
- DDRA
- SD CARD
- Hi3798MV100
- Flash
- DDRB
- USB2.0
- DDRC
- DDRD
- USB3.0
sheet 6
- 5V PLUG-IN
- CPU POWER
- Vcpu=0.92V-1.5V
- 3A
- 1%
- 1%
- 1%
- 1%
- 1%
- 3.3V POWER
- MP1484 3A
- CORE POWER
- 3A
- 0.925V
- 1%
- 1%
- Vcore=0.9V-1.32V
- 3A
- ETA1486 4A
- 1%
- VOUT=0.923*(1+26.1K/10K)=3.33V
- C44=100nF;C65=10nF;R104=5.6K;C83=3.3nF;C24=NC
- R105=26.1K;R100=10K
- MP1484 3A
- VOUT=0.925*(1+26.1K/10K)=3.34V
- 1%
- 1%
- 1%
- 1%
- C44=100nF;C65=10nF;R104=5.6K;C83=3.3nF;C24=NC;R105=26.1K;R100=10K
- DDR POWER
- Vo=0.6x(1+Rup/Rdown)=1.5V
- 2A
- 1%
- 1%
sheet 7
- Power Ctrl
- STANDBY_PWROFF
- 0
- Power Off
- 1
- Power On
sheet 8
- Unit 1 of Hi3798MV100(NAND/USB3.0/IR/SDIO/XTAL/FE)
- 1%
- 4 Layers
- R65=75ohm
- Close to Hi3798M
- 1%
- 135ohm
- 1%
- 4 Layers
- R5=22ohm
- Close to Hi3798M
- BOOT DEVICE SEL
- BOOT_SEL[1:0]
- BOOT_SEL1
- PD
- 11:eMMC
- 01:NAND Flash
- BOOT_SEL0
- PU
- 10:fSD
- System Oscillator
- PD
- PU
- ** FE PHY Design guideline **
- A.routing
- 1.Route as 100 Ohm differential impedance.
- 2.Differential pairs should be routed on TOP layer only.
- 3.Differential pairs should be separated from other traces by GND .
- B.trace length
- 1.The length for the differential pairs should be less than 5 inches.
- 2.Match trace length of RX and TX differential pairs, 10 mils max within a pair.
- C.component selection
- 1.REXT resistor should be 10K ohm +/-1%.
- 2.ESD components are suggested for ports protection,
- Put between Hi3798MV100 and transformer.
sheet 9
- Unit 2 of Hi3798MV100(JTAG/USB2.0/HDMI TX/DAC/I2S/SPI/UART)
- ** Audio & Video Design guideline **
- A.VIDEO
- 1.VIDEO REXT resistor should be 12K +/-1% precision.
- 2.REXT/COMP should be traced as short as possible,
- 1%
- and isolated from all other traces.
- B.AUDIO
- 1.VREF should be traced as short as possible,
- and isolated from all other traces.
- R51=NC,R44=10k:power up-->start
- R51=10k,R44=NC:power up-->pull key-->start
- NOTE:EMI-1000ohm or 600ohm@100MHz
- 135ohm
- 1%
- USB0:usb_boot/adb
- ** USB Design guideline **
- A.routing
- 1.Route as 90 Ohm differential impedance.
- 2.Differential pairs should be routed on TOP layer only.
- 3.Differential pairs should be separated from other traces by GND .
- B.trace length
- 1.The length for the differential pairs should be less than 5 inches.
- 2.Match trace length of DP and DM differential pairs, 10 mils max within a pair.
- C.component selection
- 1.USB2.0 REXT resistor should be 135 ohm +/-1% and USB3.0 200 ohm +/-1%
- 2.ESD components are suggested for ports protection.
- 3.Equivalent capacitance of ESD component should be < 1.5pF.
